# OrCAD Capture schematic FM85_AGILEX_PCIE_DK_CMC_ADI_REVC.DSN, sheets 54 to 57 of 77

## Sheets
54 PWR - VCC -1: size Custom
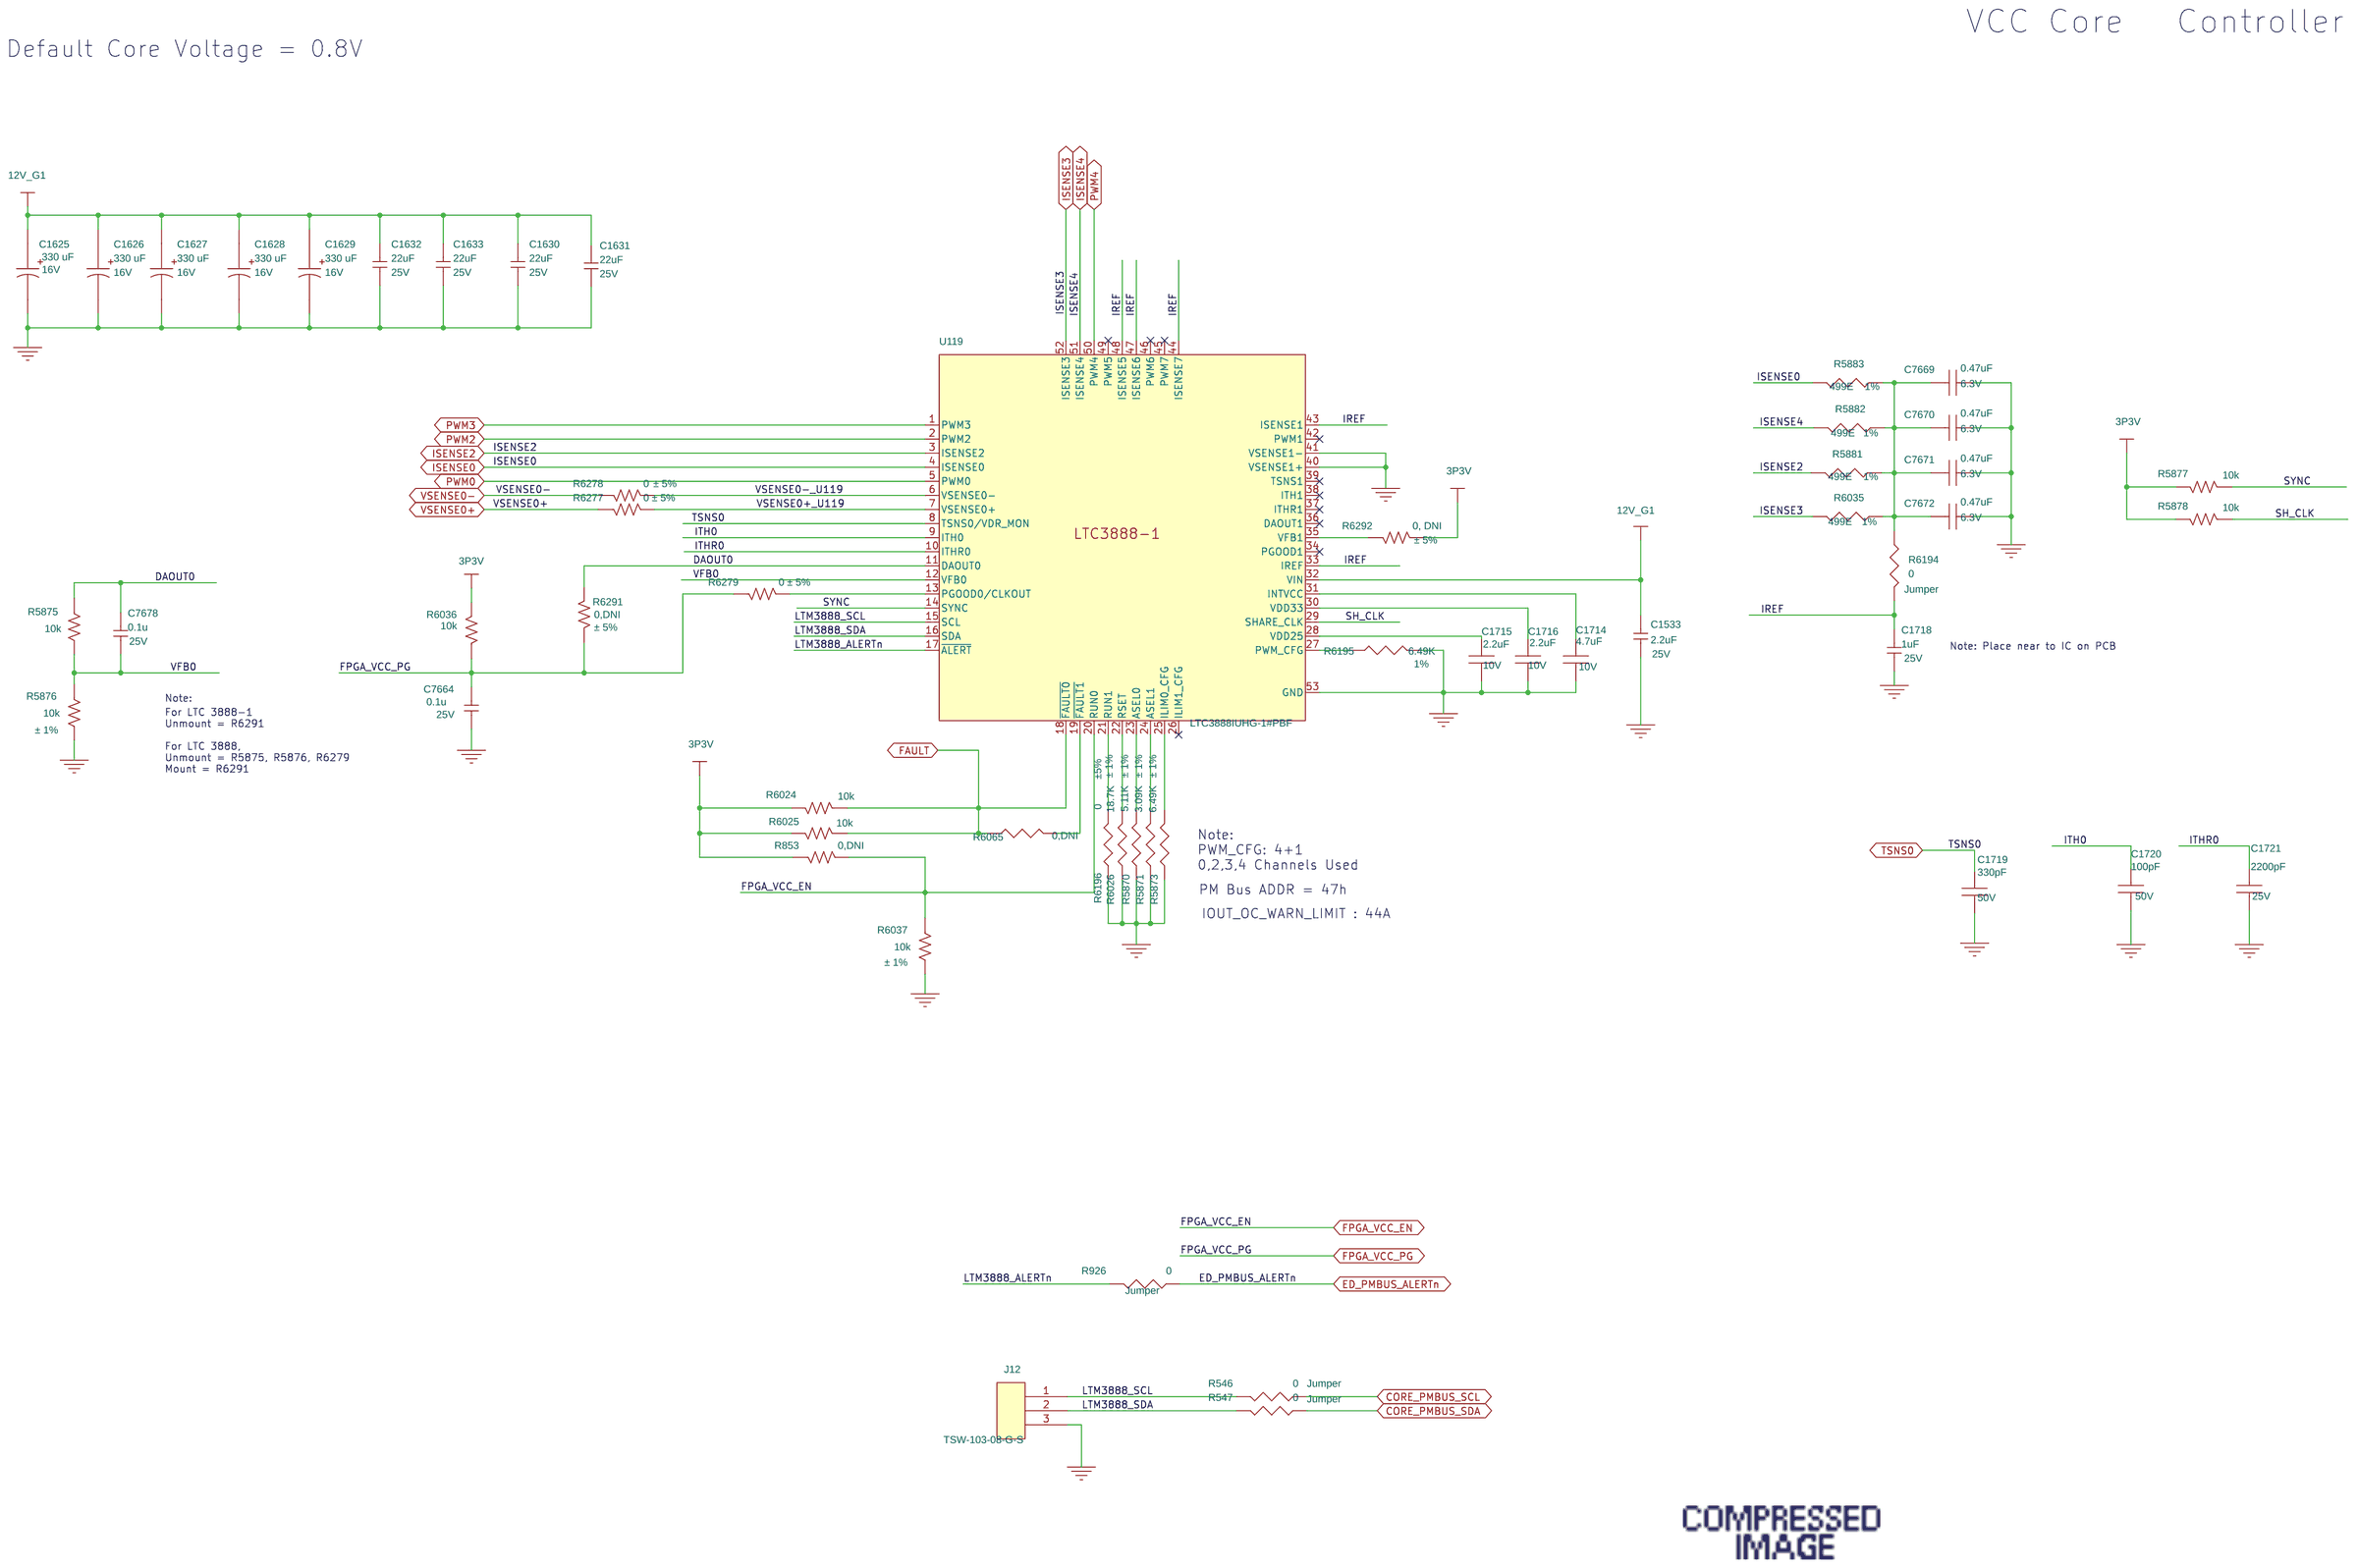
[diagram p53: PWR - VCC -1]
55 PWR - VCC -2: size Custom
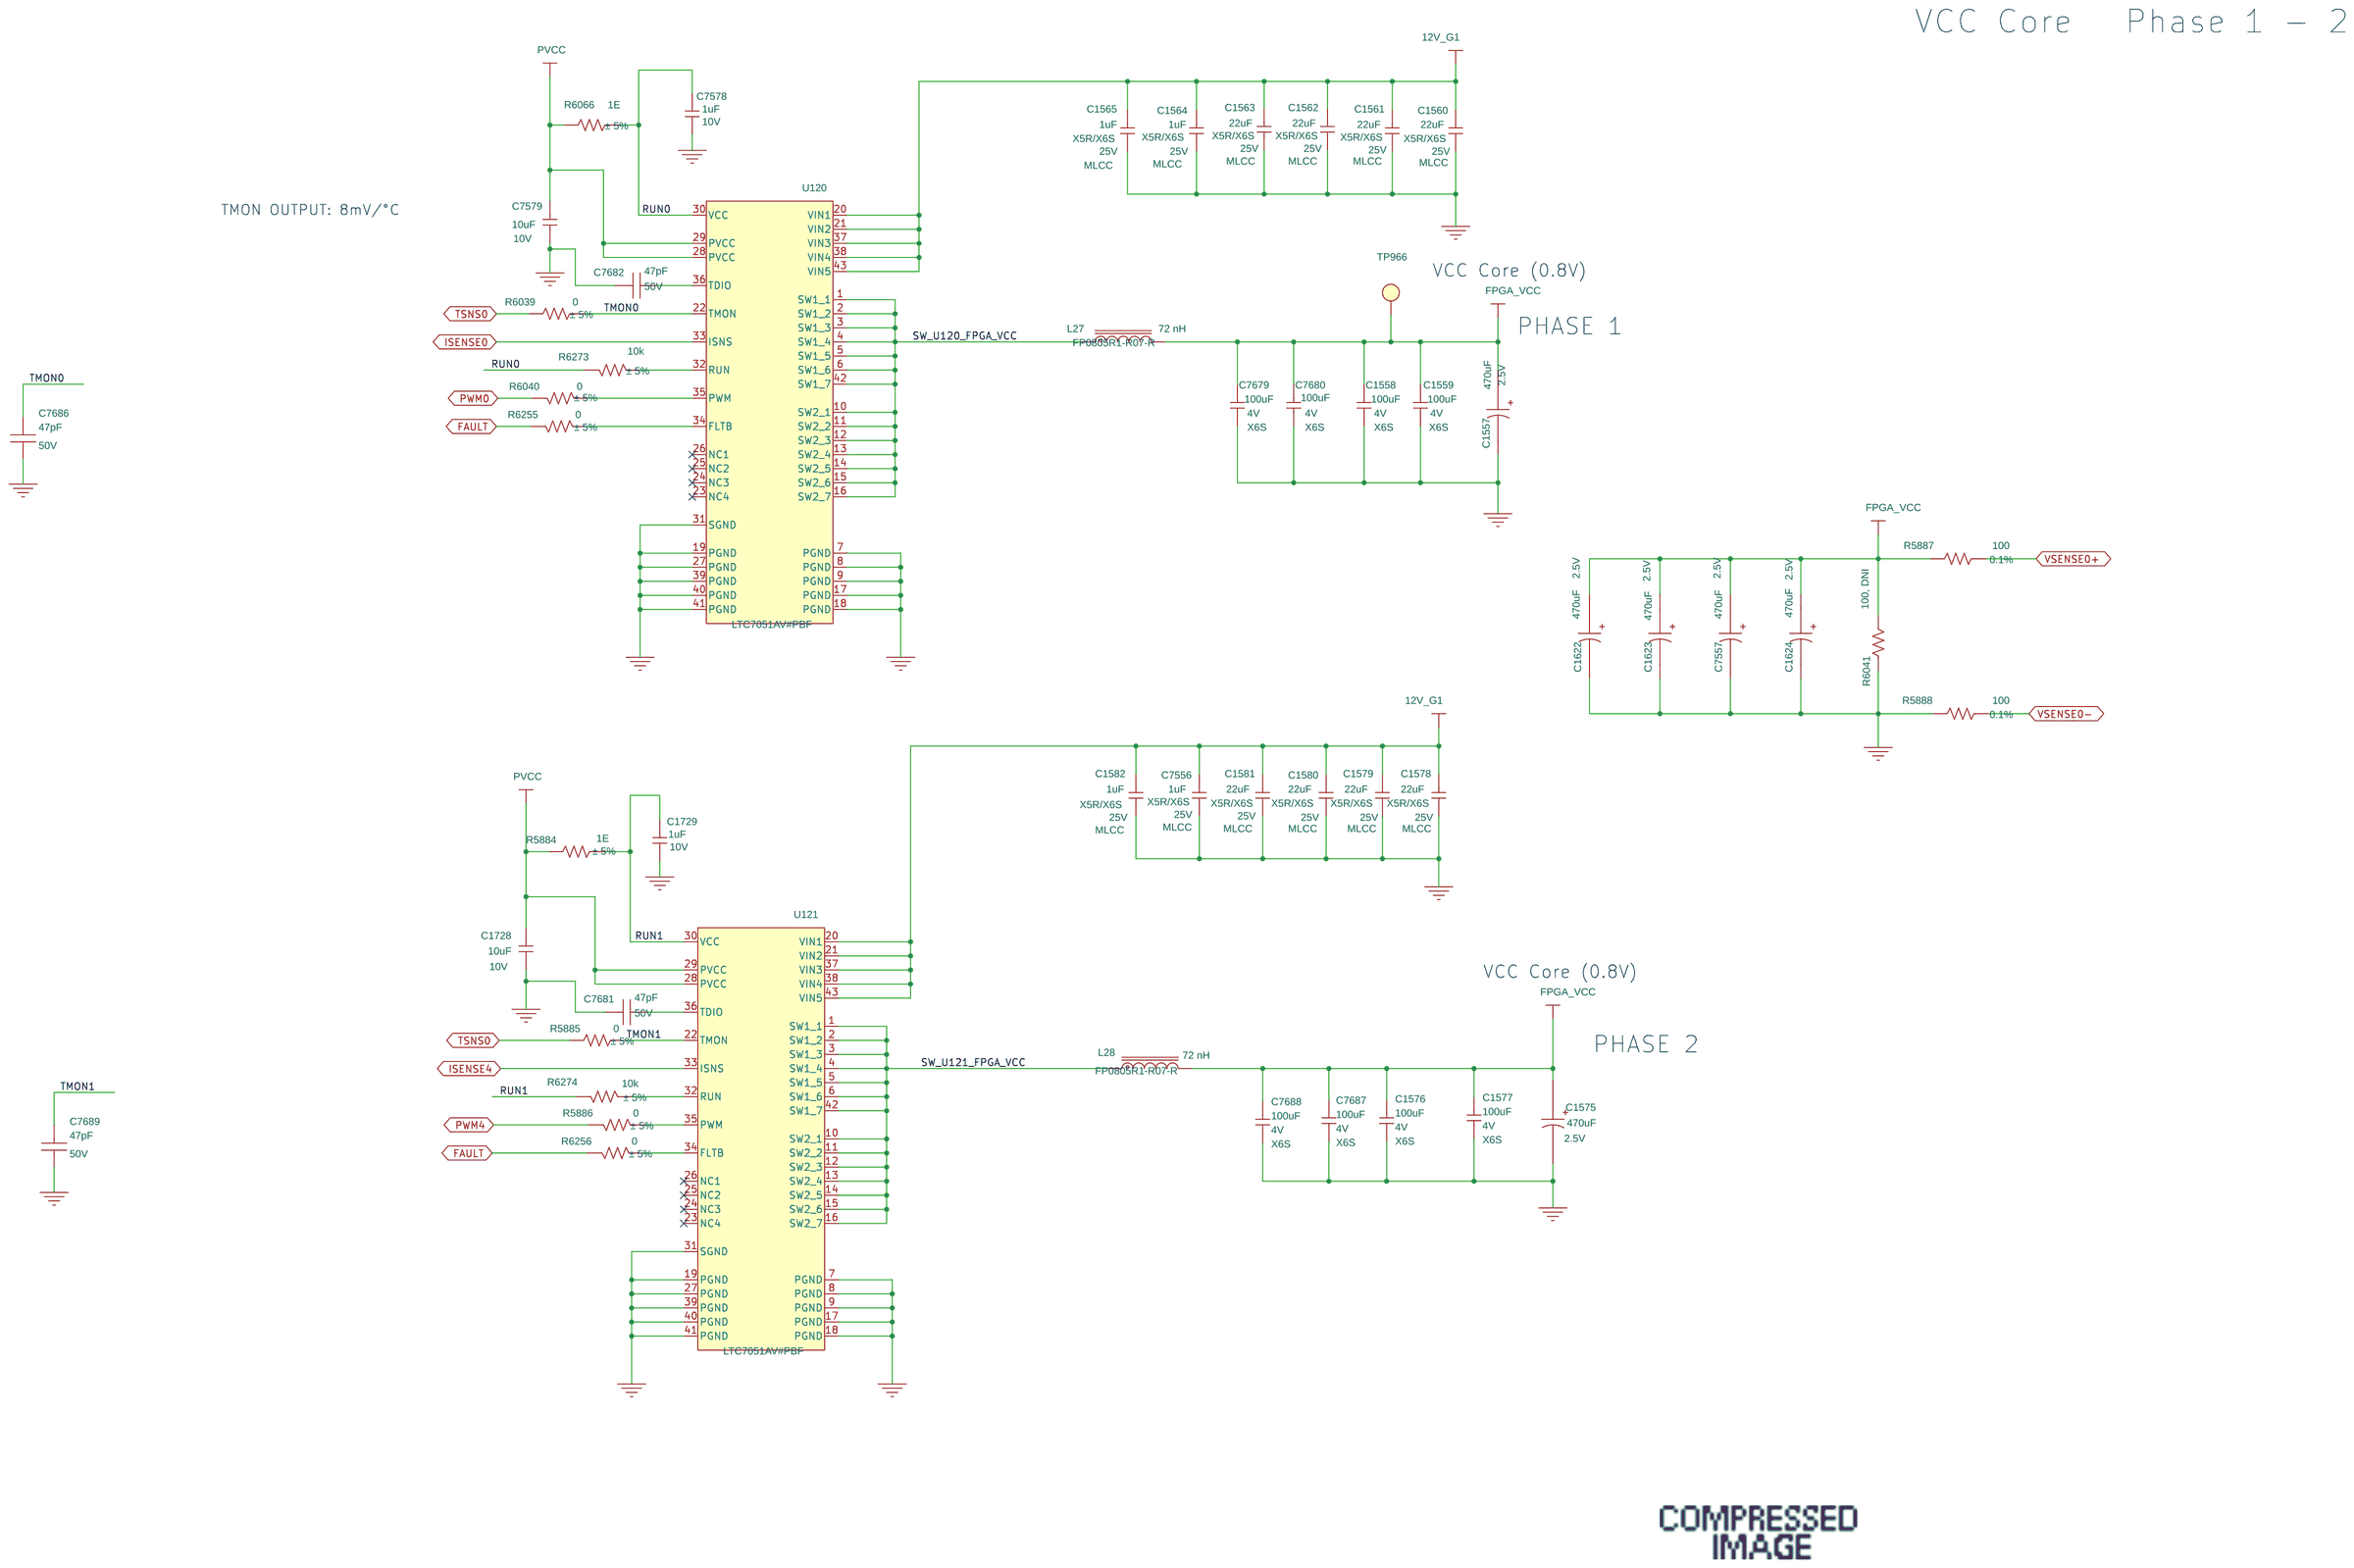
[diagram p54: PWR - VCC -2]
56 PWR - VCC - 3: size Custom
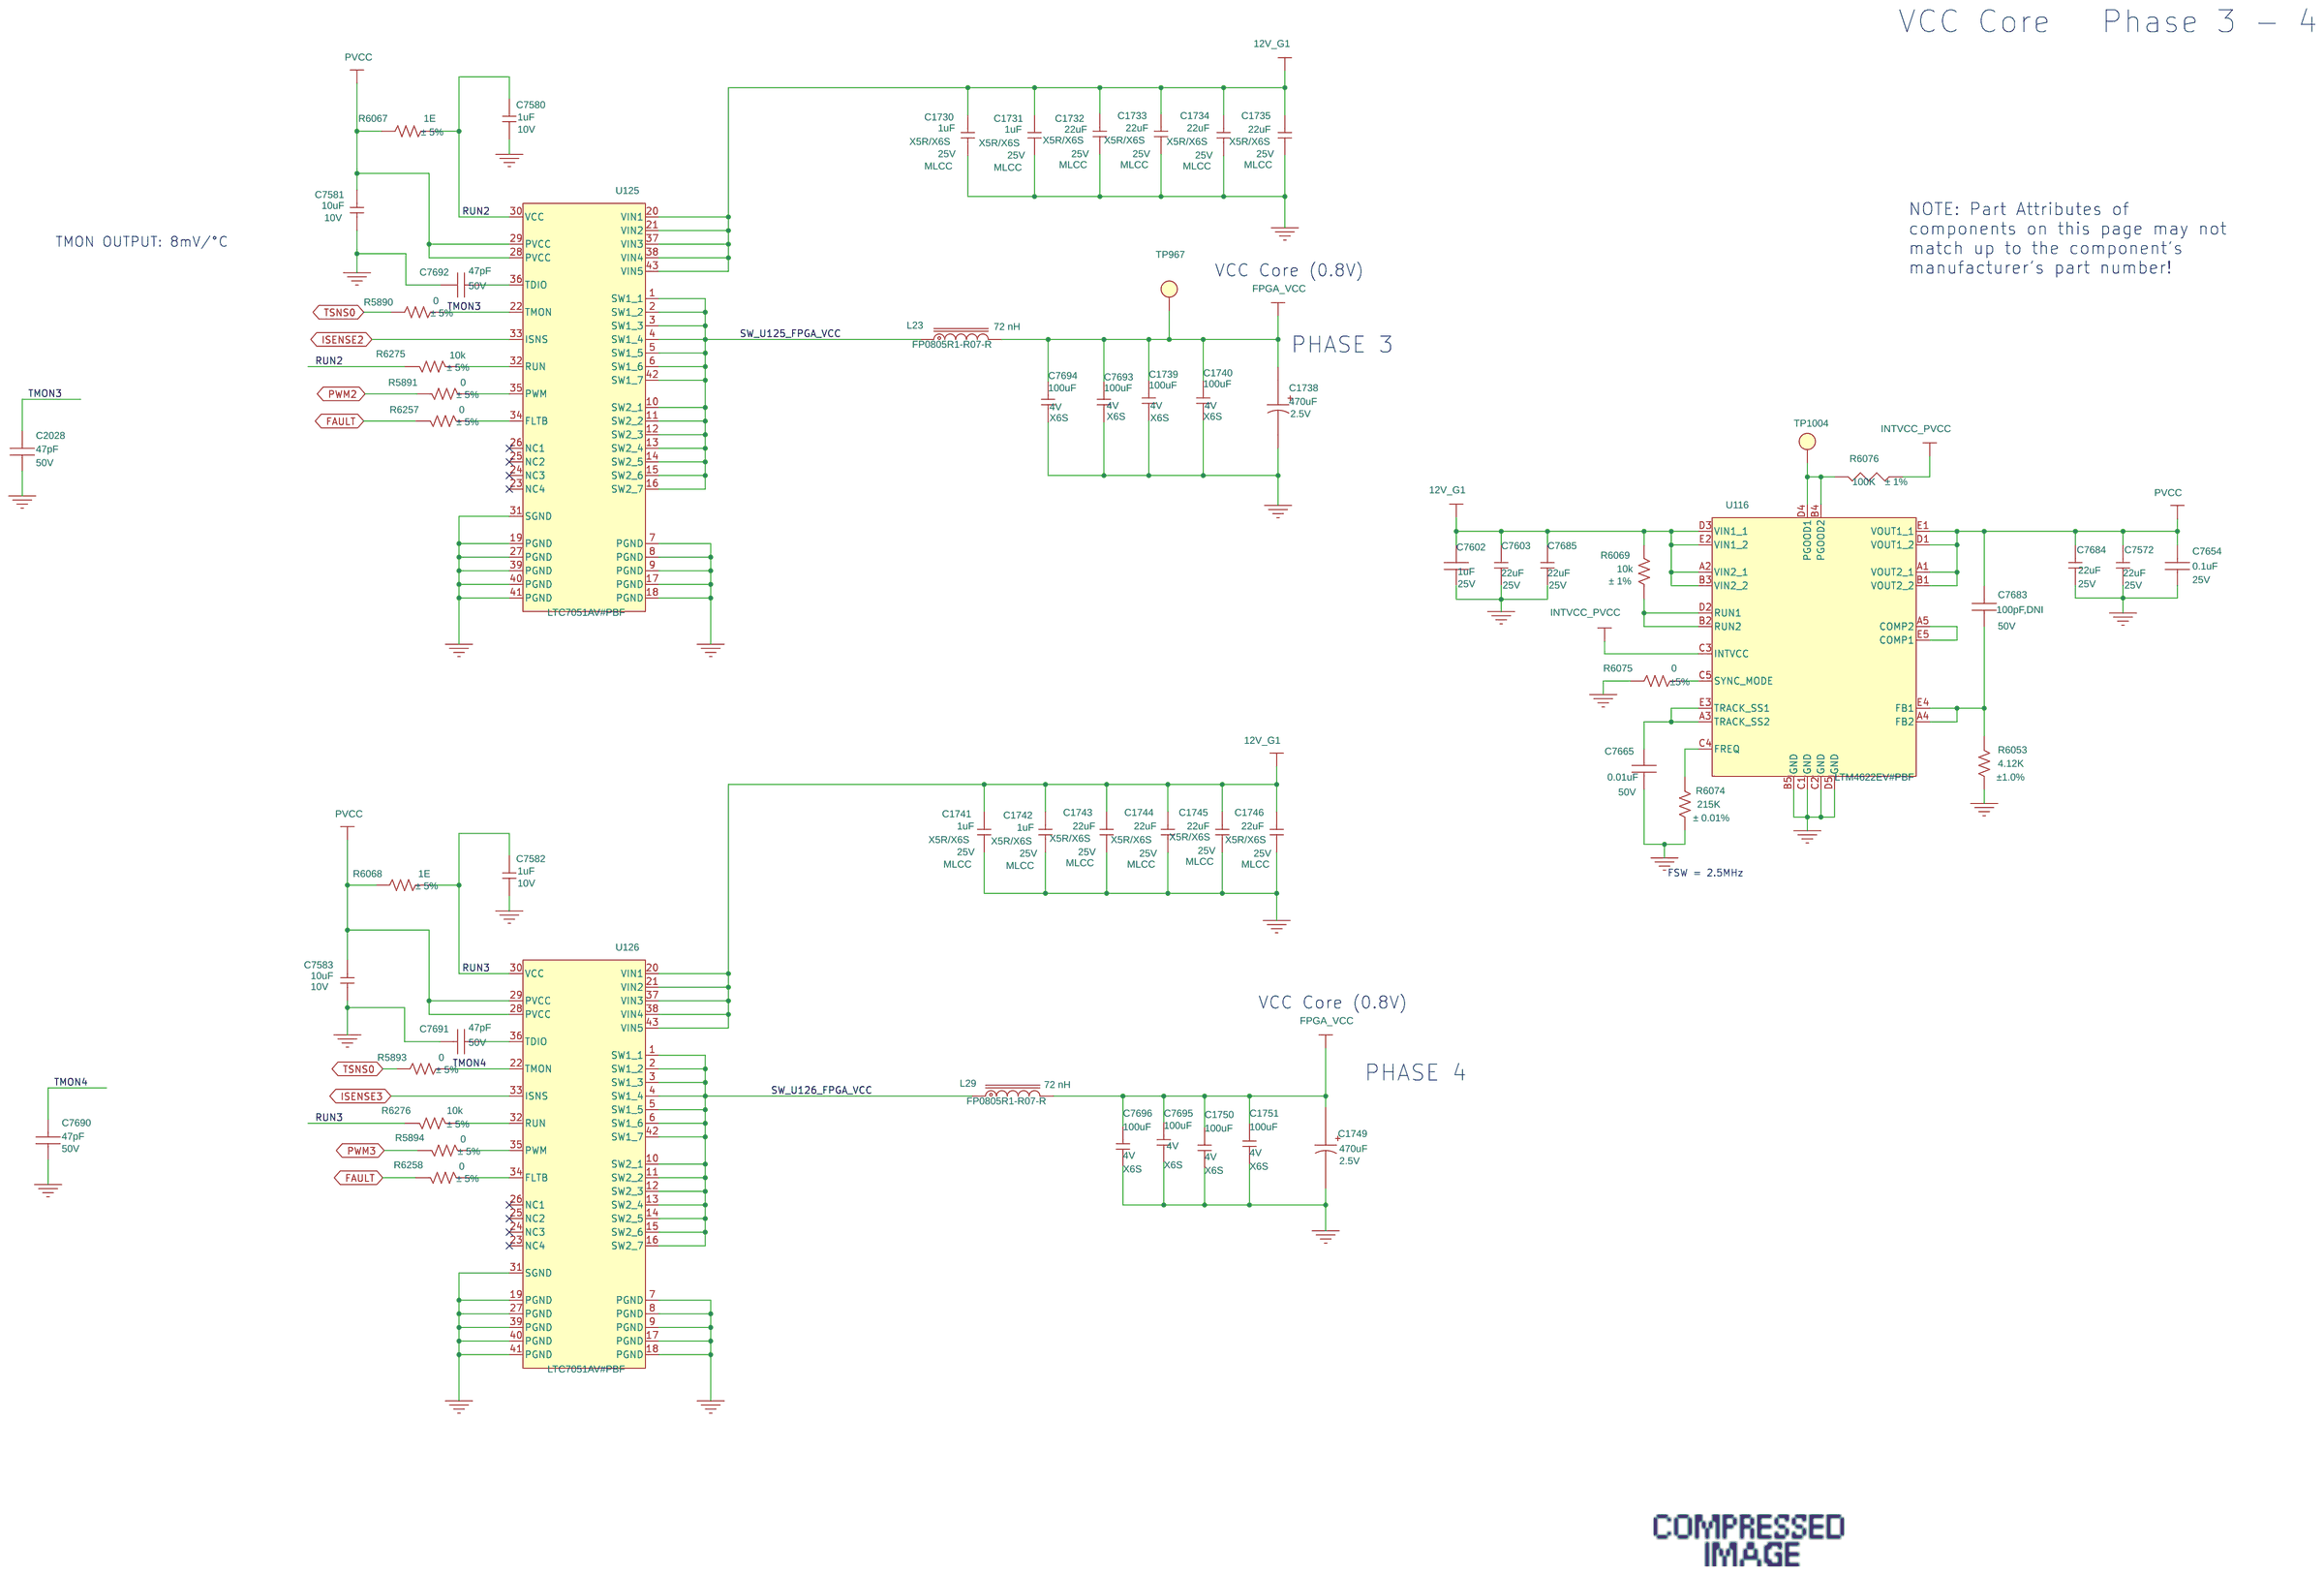
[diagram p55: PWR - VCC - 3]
57 PWR - 12V to 5V: size C
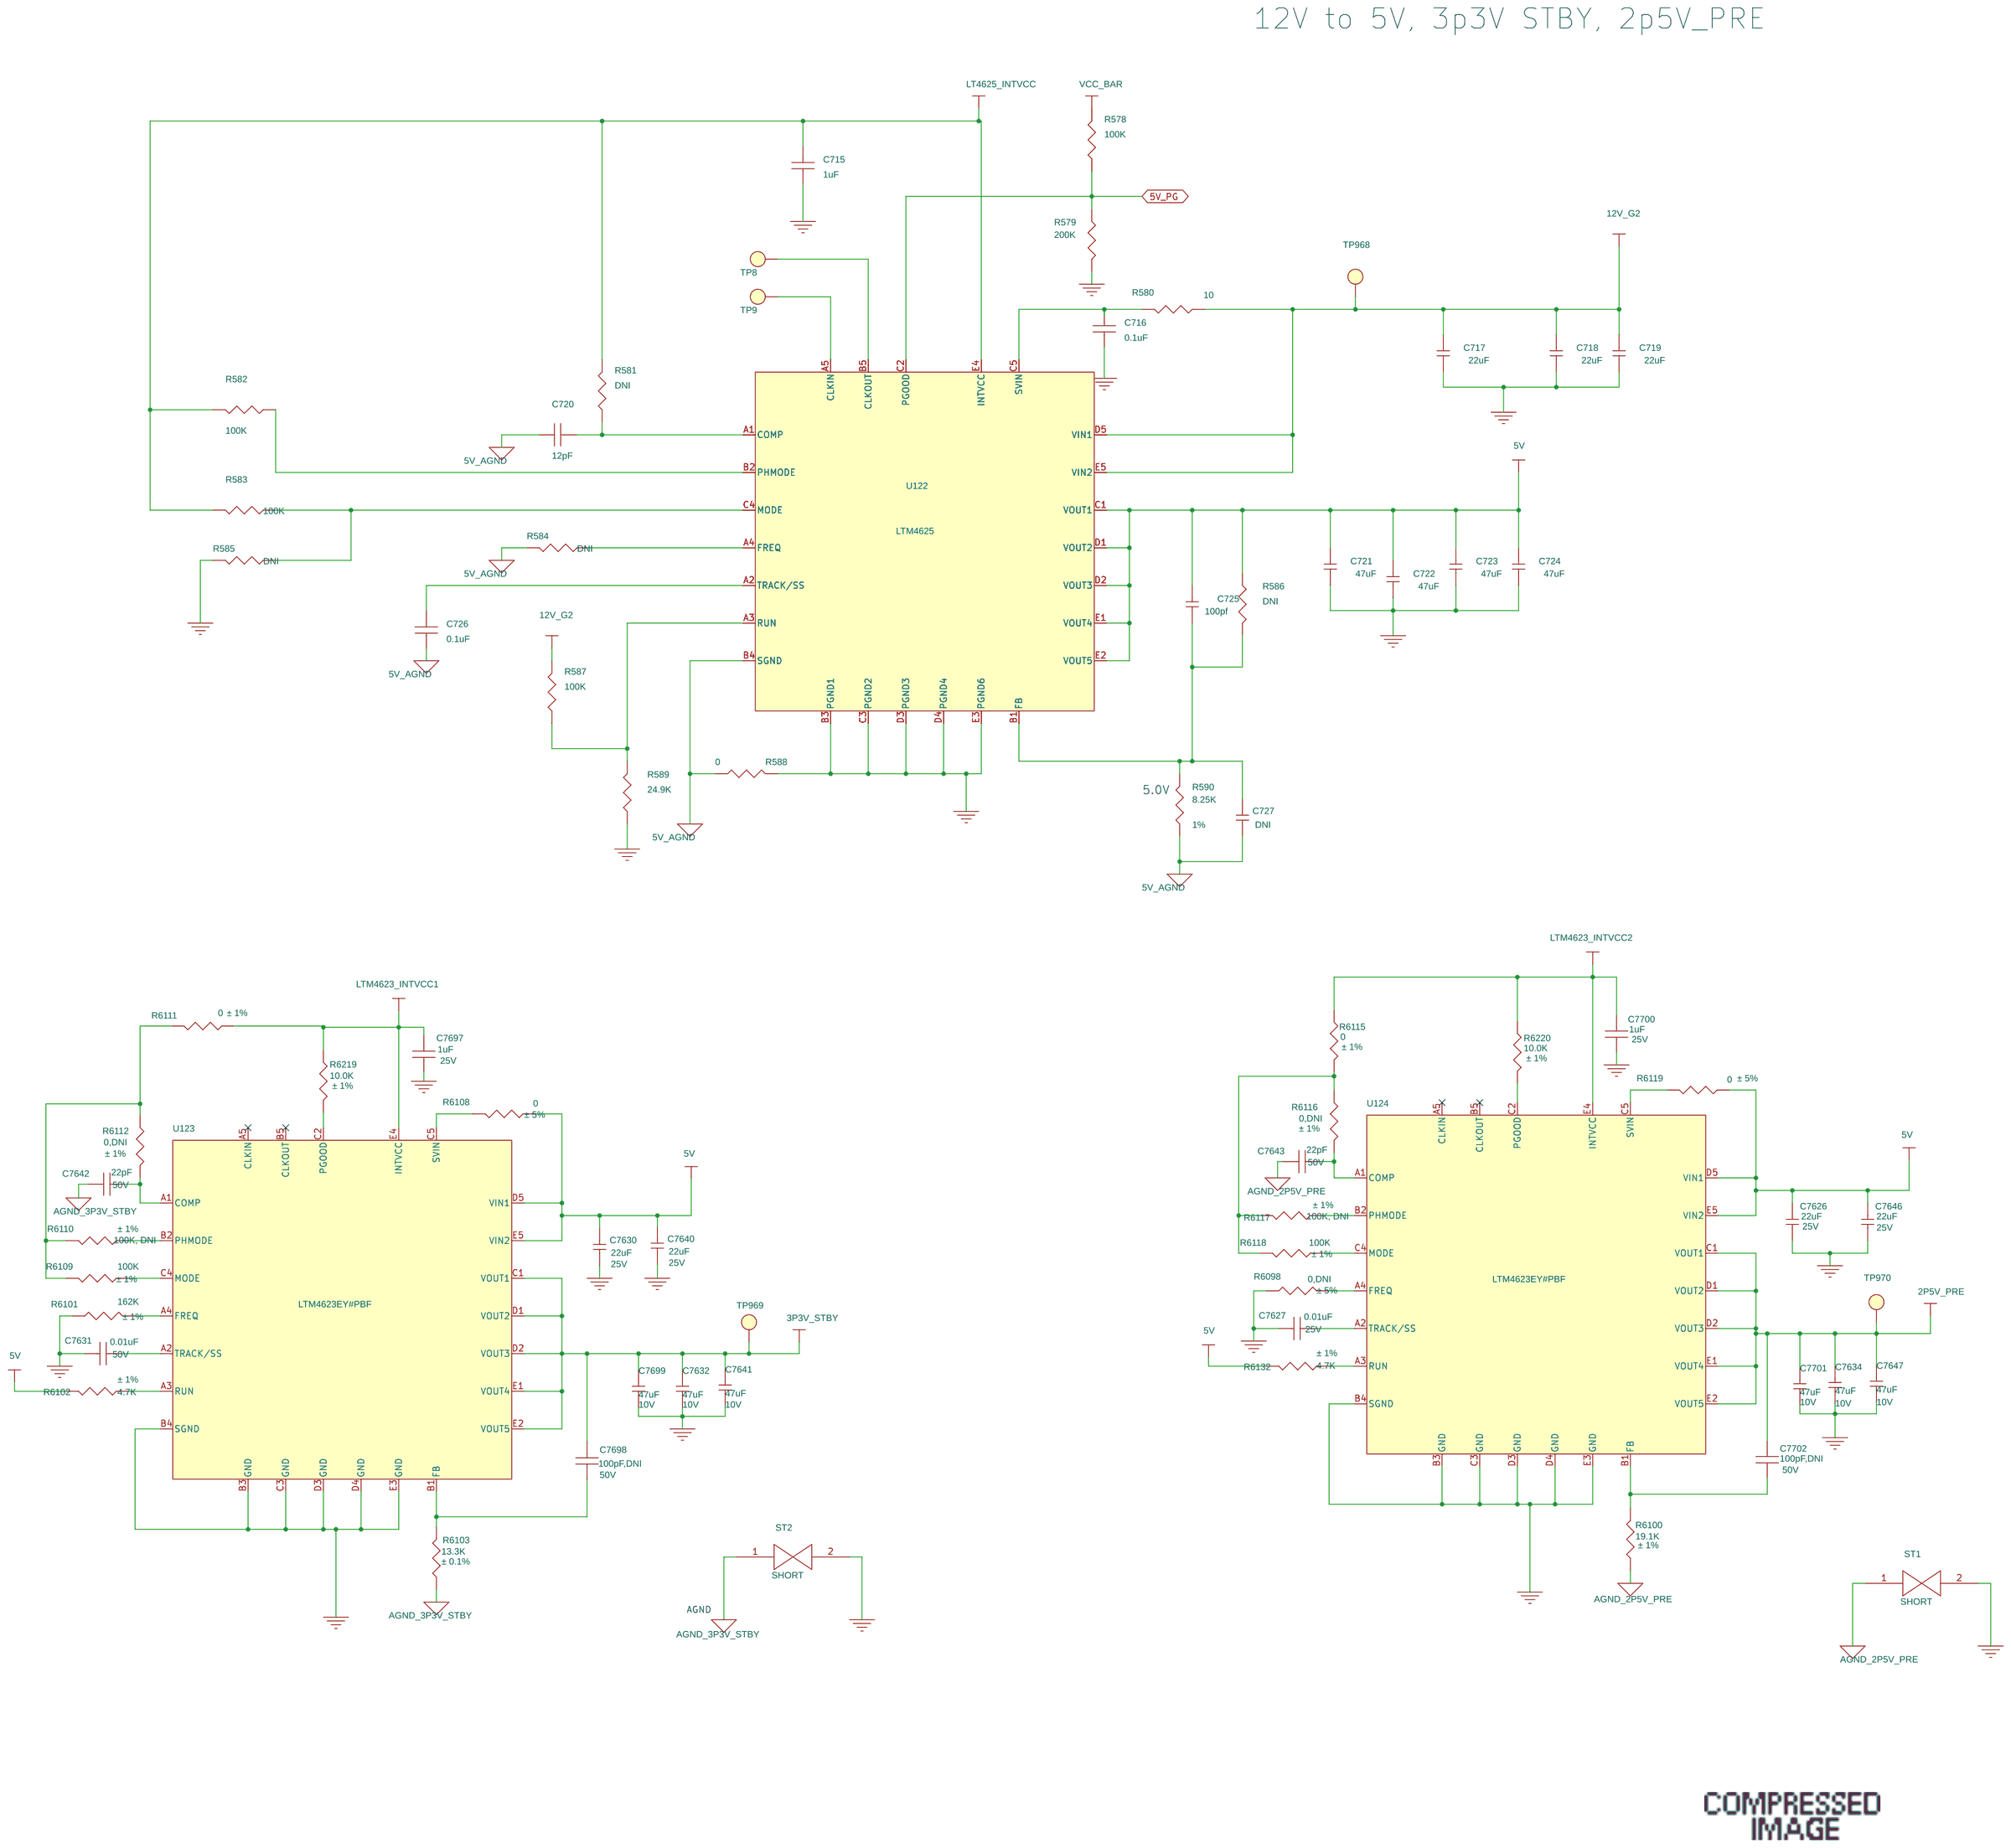
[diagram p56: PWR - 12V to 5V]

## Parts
sheet PWR - 12V to 5V
C715  1uF  [0402]
C716  0.1uF  [0402]
C717  22uF  [1206]
C718  22uF  [1206]
C719  22uF  [1206]
C720  12pF  [0402]
C721  47uF  [1206]
C722  47uF  [1206]
C723  47uF  [1206]
C724  47uF  [1206]
C725  100pf  [0402]
C726  0.1uF  [0402]
C727  DNI  [C0402]
C7626  22uF  [1206]
C7627  0.01uF  [0402]
C7630  22uF  [1206]
C7631  0.01uF  [0402]
C7632  47uF  [C1206]
C7634  47uF  [C1206]
C7640  22uF  [1206]
C7641  47uF  [C1206]
C7642  22pF  [0603]
C7643  22pF  [0603]
C7646  22uF  [1206]
C7647  47uF  [C1206]
C7697  1uF  [0402]
C7698  100pF,DNI  [0402]
C7699  47uF  [C1206]
C7700  1uF  [0402]
C7701  47uF  [C1206]
C7702  100pF,DNI  [0402]
R578  100K  [0402]
R579  200K  [0402]
R580  10  [0402]
R581  DNI  [0402]
R582  100K  [0402]
R583  100K  [0402]
R584  DNI  [0402]
R585  DNI  [0402]
R586  DNI  [0402]
R587  100K  [0402]
R588  0  [0402]
R589  24.9K  [0402]
R590  8.25K  [0402]
R6098  0,DNI  [0402]
R6100  19.1K  [0402]
R6101  162K  [RC0402]
R6102  4.7K  [0402]
R6103  13.3K  [0402]
R6108  0  [0402]
R6109  100K  [0402]
R6110  100K, DNI  [0402]
R6111  0  [0402]
R6112  0,DNI  [0402]
R6115  0  [0402]
R6116  0,DNI  [0402]
R6117  100K, DNI  [0402]
R6118  100K  [0402]
R6119  0  [0402]
R6132  4.7K  [0402]
R6219  10.0K  [0402]
R6220  10.0K  [0402]
ST1  SHORT  [SHORT]
ST2  SHORT  [SHORT]
TP8  TESTPOINT  [30MIL_TP]
TP9  TESTPOINT  [30MIL_TP]
TP968  TESTPOINT  [30MIL_TP]
TP969  TESTPOINT  [30MIL_TP]
TP970  TESTPOINT  [30MIL_TP]
U122  LTM4625  [BGA25]
U123  LTM4623EY#PBF  [BGA25C127P5X5_625X625X262]
U124  LTM4623EY#PBF  [BGA25C127P5X5_625X625X262]
sheet PWR - VCC -1
C1533  2.2uF  [0402]
C1625  330 uF  [CT7343-43]
C1626  330 uF  [CT7343-43]
C1627  330 uF  [CT7343-43]
C1628  330 uF  [CT7361-20]
C1629  330 uF  [CT7343-43]
C1630  22uF  [CAPC3216X135L50N]
C1631  22uF  [CAPC3216X135L50N]
C1632  22uF  [CAPC3216X135L50N]
C1633  22uF  [CAPC3216X135L50N]
C1714  4.7uF  [0402]
C1715  2.2uF  [0603]
C1716  2.2uF  [0603]
C1718  1uF  [0402]
C1719  330pF  [0603]
C1720  100pF  [0402]
C1721  2200pF  [0402]
C7664  0.1u  [CAPC1005X60L20L]
C7669  0.47uF  [0402]
C7670  0.47uF  [0402]
C7671  0.47uF  [0402]
C7672  0.47uF  [0402]
C7678  0.1u  [CAPC1005X60L20L]
J12  TSW-103-08-G-S  [1x3_HDR_TH]
R546  0  [0402]
R547  0  [0402]
R853  0,DNI  [RESC1005X40L20L]
R926  0  [0402]
R5870  5.11K  [0402]
R5871  3.09K  [0402]
R5873  6.49K  [0402]
R5875  10k  [0402]
R5876  10k  [0402]
R5877  10k  [0402]
R5878  10k  [0402]
R5881  499E  [0402]
R5882  499E  [0402]
R5883  499E  [0402]
R6024  10k  [0402]
R6025  10k  [0402]
R6026  18.7K  [0402]
R6035  499E  [0402]
R6036  10k  [0402]
R6037  10k  [0402]
R6065  0,DNI  [0402]
R6194  0  [0402]
R6195  6.49K  [0402]
R6196  0  [0402]
R6277  0  [RESC1005X40L20L]
R6278  0  [RESC1005X40L20L]
R6279  0  [RESC1005X40L20L]
R6291  0,DNI  [RESC1005X40L20L]
R6292  0, DNI  [RESC1005X40L20L]
U119  LTC3888IUHG-1#PBF  [QFN40P500X800X80-53N]
sheet PWR - VCC -2
C1557  470uF  [CAPMP7343X300L130X240N_p079in]
C1558  100uF  [CAPC2012X110L50L]
C1559  100uF  [CAPC2012X110L50L]
C1560  22uF  [CAPC3216X135L50N]
C1561  22uF  [CAPC3216X135L50N]
C1562  22uF  [CAPC3216X135L50N]
C1563  22uF  [CAPC3216X135L50N]
C1564  1uF  [capc1005x60l20l]
C1565  1uF  [capc1005x60l20l]
C1575  470uF  [CAPMP7343X300L130X240N_p079in]
C1576  100uF  [CAPC2012X110L50L]
C1577  100uF  [CAPC2012X110L50L]
C1578  22uF  [CAPC3216X135L50N]
C1579  22uF  [CAPC3216X135L50N]
C1580  22uF  [CAPC3216X135L50N]
C1581  22uF  [CAPC3216X135L50N]
C1582  1uF  [capc1005x60l20l]
C1622  470uF  [CAPMP7343X300L130X240N_p079in]
C1623  470uF  [CAPMP7343X300L130X240N_p079in]
C1624  470uF  [CAPMP7343X300L130X240N_p079in]
C1728  10uF  [0402]
C1729  1uF  [0402]
C7556  1uF  [capc1005x60l20l]
C7557  470uF  [CAPMP7343X300L130X240N_p079in]
C7578  1uF  [0402]
C7579  10uF  [0402]
C7679  100uF  [CAPC2012X110L50L]
C7680  100uF  [CAPC2012X110L50L]
C7681  47pF  [0402]
C7682  47pF  [0402]
C7686  47pF  [0402]
C7687  100uF  [CAPC2012X110L50L]
C7688  100uF  [CAPC2012X110L50L]
C7689  47pF  [0402]
L27  72 nH  [IND_FP0805-CUS]
L28  72 nH  [IND_FP0805-CUS]
R5884  1E  [RESC1005X40L20L]
R5885  0  [RESC1005X40L20L]
R5886  0  [RESC1005X40L20L]
R5887  100  [RESC1005X40L20L]
R5888  100  [RESC1005X40L20L]
R6039  0  [RESC1005X40L20L]
R6040  0  [RESC1005X40L20L]
R6041  100, DNI  [RESC1608X60L27N]
R6066  1E  [RESC1005X40L20L]
R6255  0  [RESC1005X40L20L]
R6256  0  [RESC1005X40L20L]
R6273  10k  [0402]
R6274  10k  [0402]
TP966  TESTPOINT  [30MIL_TP]
U120  LTC7051AV#PBF  [ANALOG_LQFN-42P]
U121  LTC7051AV#PBF  [ANALOG_LQFN-42P]
sheet PWR - VCC - 3
C1730  1uF  [0402]
C1731  1uF  [0402]
C1732  22uF  [CAPC3216X135L50N]
C1733  22uF  [CAPC3216X135L50N]
C1734  22uF  [CAPC3216X135L50N]
C1735  22uF  [CAPC3216X135L50N]
C1738  470uF  [CAPMP7343X300L130X240N_p079in]
C1739  100uF  [CAPC2012X110L50L]
C1740  100uF  [CAPC2012X110L50L]
C1741  1uF  [0402]
C1742  1uF  [0402]
C1743  22uF  [CAPC3216X135L50N]
C1744  22uF  [CAPC3216X135L50N]
C1745  22uF  [CAPC3216X135L50N]
C1746  22uF  [CAPC3216X135L50N]
C1749  470uF  [CAPMP7343X300L130X240N_p079in]
C1750  100uF  [CAPC2012X110L50L]
C1751  100uF  [CAPC2012X110L50L]
C2028  47pF  [0402]
C7572  22uF  [CAPC3216X135L50N]
C7580  1uF  [0402]
C7581  10uF  [0402]
C7582  1uF  [0402]
C7583  10uF  [0402]
C7602  1uF  [0402]
C7603  22uF  [CAPC3216X135L50N]
C7654  0.1uF  [0402]
C7665  0.01uF  [0402]
C7683  100pF,DNI  [0402]
C7684  22uF  [CAPC3216X135L50N]
C7685  22uF  [CAPC3216X135L50N]
C7690  47pF  [0402]
C7691  47pF  [0402]
C7692  47pF  [0402]
C7693  100uF  [CAPC2012X110L50L]
C7694  100uF  [CAPC2012X110L50L]
C7695  100uF  [CAPC2012X110L50L]
C7696  100uF  [CAPC2012X110L50L]
L23  72 nH  [IND_FP0805-CUS]
L29  72 nH  [IND_FP0805-CUS]
R5890  0  [RESC1005X40L20L]
R5891  0  [RESC1005X40L20L]
R5893  0  [RESC1005X40L20L]
R5894  0  [RESC1005X40L20L]
R6053  4.12K  [0402]
R6067  1E  [RESC1005X40L20L]
R6068  1E  [RESC1005X40L20L]
R6069  10k  [0402]
R6074  215K  [0402]
R6075  0  [RESC1005X40L20L]
R6076  100K  [0402]
R6257  0  [RESC1005X40L20L]
R6258  0  [RESC1005X40L20L]
R6275  10k  [0402]
R6276  10k  [0402]
TP967  TESTPOINT  [30MIL_TP]
TP1004  TESTPOINT  [30MIL_TP]
U116  LTM4622EV#PBF  [LGA25C127P5X5_625X625X192N]
U125  LTC7051AV#PBF  [ANALOG_LQFN-42P]
U126  LTC7051AV#PBF  [ANALOG_LQFN-42P]

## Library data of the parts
C715 = CAP: CAP - CER, 1UF, 25V, 10%, X5R, 0402; Item Num: H29050-001; Lead Free Status: Yes; Manufacturer: TDK Electronics; Manufacturer Part Num: CGB2A1X5R1E105K033BC; Num Pins: 2; Part Class: CAPACITORS; RoHS Compliant: Yes
C716 C726 = CAP: CAPC,  X7R, 0402, 0.1uF, 25V, ±20%; AGILE_LINK: http://sj-agile9app/Agile/PLMServlet?action=OpenEmailObject&classid=10000&objid=213459527; Item Num: K13660-001; LIFECYCLE_PHASE: Active; Lead Free Status: Lead Free; MFR_LIFECYCLE: Active; Manufacturer: Murata; Manufacturer Part Num: GRM155R71E104KE14D; Num Pins: 2; PART_SUBCLASS: CAPACITORS; Part Class: CAPACITORS; RATED_VOLTAGE: 25V; RoHS Compliant: RoHS Compliant; TOLERANCE: +80%/-20%
C717-C719 = Cap,_NP,_1206: CAP - CER, 22UF, 25V, 10%, X5R, 1206; Item Num: K28232-001; Manufacturer: Murata; Manufacturer Part Num: GRM31CR61E226KE15L
C720 = CAP: CAP - 12PF, 50V, +/-5%, CERAMIC, 0402 SMD; AGILE_LINK: http://sj-agile9app/Agile/PLMServlet?action=OpenEmailObject&classid=10000&objid=257385742; Item Num: A36095-043; LIFECYCLE_PHASE: Active; Lead Free Status: Lead Free; MFR_LIFECYCLE: Active; Manufacturer: Murata; Manufacturer Part Num: GRM1555C1H120JA01D; Num Pins: 2; PART_SUBCLASS: CAPACITORS; RATED_VOLTAGE: 50V; RoHS Compliant: RoHS Compliant; TOLERANCE: +/-5%
C721-C724 = Cap,_NP,_1206: CAP - CER 47UF 10V 20% X5R 1206; Item Num: K13655-001; Manufacturer: TDK Electronics; Manufacturer Part Num: C3216X5R1A476M160AB
C725 = Cap,_NP,_0402: CAP, CERAMIC, 100pF, 0402, 5%, 50VDC, NPO; Item Num: K13768-001; Manufacturer: Murata; Manufacturer Part Num: GRM1555C1H101JA01D
C727 = Cap,_NP,_0402: CAP - CER, 15PF, 50V, +/-5%, C0G, 0402 SMD; Item Num: A36095-047; Manufacturer: Murata; Manufacturer Part Num: GRM1555C1H150JA01D
C7626 C7630 C7640 C7646 = Cap,_NP,_1206: CAP - CER, 22UF, 25V, 10%, X5R, 1206; Item Num: K28232-001; Manufacturer: Murata; Manufacturer Part Num: GRM31CR61E226KE15L; RATED_VOLTAGE: 25V
C7627 = CAP: CAP - CER, 10NF, 50V, +/-10%, X7R, 0402 SMD; CAPACITANCE: 0.1uF; Item Num: A36096-100; LIFECYCLE_PHASE: Active; Lead Free Status: Lead Free; MFR_LIFECYCLE: Active; Manufacturer: Murata; Manufacturer Part Num: GRM155R71H103KA88D; Num Pins: 2; PART_SUBCLASS: CAPACITORS; Part Class: CAPACITORS; RATED_VOLTAGE: 25V; RoHS Compliant: RoHS Compliant
C7631 = CAP: CAP - CER, 10NF, 50V, +/-10%, X7R, 0402 SMD; CAPACITANCE: 0.1uF; Item Num: A36096-100; LIFECYCLE_PHASE: Active; Lead Free Status: Lead Free; MFR_LIFECYCLE: Active; Manufacturer: Murata; Manufacturer Part Num: GRM155R71H103KA88D; Num Pins: 2; PART_SUBCLASS: CAPACITORS; Part Class: CAPACITORS; RATED_VOLTAGE: 50V; RoHS Compliant: RoHS Compliant
C7632 C7634 C7641 C7647 C7699 C7701 = Cap,_NP,_1206: CAP - CER 47UF 10V 20% X5R 1206; Item Num: K13655-001; Manufacturer: TDK Electronics; Manufacturer Part Num: C3216X5R1A476M160AB; RATED_VOLTAGE: 10V
C7642 C7643 = CAP_NP: CAPC,C0G,0603,22.000PF,50.000V,+/- 5%,; Item Num: M23241-001; Manufacturer: Murata; Manufacturer Part Num: GRM1885C1H220JA01J; RATED_VOLTAGE: 50V
C7697 C7700 = CAP: CAP - CER, 1UF, 25V, 10%, X5R, 0402; Item Num: H29050-001; Lead Free Status: Yes; Manufacturer: TDK Electronics; Manufacturer Part Num: CGB2A1X5R1E105K033BC; Num Pins: 2; Part Class: CAPACITORS; RATED_VOLTAGE: 25V; RoHS Compliant: Yes
C7698 = CAP: CAP CER 100PF 50V X7R 0402; CAPACITANCE: 1000pF; Dielectric: X7R; IPN No: A36095-026; Item Num: A36095-026; LIFECYCLE_PHASE: Active; Lead Free Status: Lead Free; Manufacturer: AVX; Manufacturer Part Num: 04025C101KAT2A; Num Pins: 2; Part Class: CAPACITORS; RATED_VOLTAGE: 50V; RoHS Compliant: RoHS Compliant; Tolerance: 10%
C7702 = CAP: CAP, CERAMIC, 100pF, 0402, 5%, 50VDC, NPO; CAPACITANCE: 1000pF; Dielectric: X7R; IPN No: A36095-026; Item Num: A36095-026; LIFECYCLE_PHASE: Active; Lead Free Status: Lead Free; Manufacturer: Murata; Manufacturer Part Num: 04025C101KAT2A; Num Pins: 2; Part Class: CAPACITORS; RATED_VOLTAGE: 50V; RoHS Compliant: RoHS Compliant; Tolerance: 10%
R578 R582 R583 R587 = RESISTOR: RES, 100K OHMS, 1.0%, 1/16W, 0402; AGILE_LINK: http://sj-agile9app/Agile/PLMServlet?action=OpenEmailObject&classid=10000&objid=146932246; Item Num: E86804-001; LIFECYCLE_PHASE: Active; MFR_LIFECYCLE: Active; Manufacturer: Panasonic; Manufacturer Part Num: ERJ-2RKF1003X; Num Pins: 2; PART_SUBCLASS: RESISTORS; POWER: 1/10W; RoHS Compliant: RoHS Compliant; TOLERANCE: +/-1%
R579 = RES: RES - 200K OHM, 1/16W, 1%, 0402 SMD; Item Num: A93548-186; Manufacturer: Panasonic; Manufacturer Part Num: ERJ-2RKF2003X; Package: SMD; Part Class: RESISTORS; Type: Resistor
R580 = RESISTOR: RES, 10 OHM, 1%, 1/16W, 0402; AGILE_LINK: http://sj-agile9app/Agile/PLMServlet?action=OpenEmailObject&classid=10000&objid=146932246; Item Num: A80345-001; LIFECYCLE_PHASE: Active; MFR_LIFECYCLE: Active; Manufacturer: Panasonic; Manufacturer Part Num: ERJ-2RKF10R0X; Num Pins: 2; PART_SUBCLASS: RESISTORS; POWER: 1/16W; RoHS Compliant: RoHS Compliant; TOLERANCE: +/-1%
R581 R584-R586 = RESISTOR: RES, 100K OHMS, 1.0%, 1/16W, 0402; AGILE_LINK: http://sj-agile9app/Agile/PLMServlet?action=OpenEmailObject&classid=10000&objid=146932246; Item Num: E86804-001; LIFECYCLE_PHASE: Active; MFR_LIFECYCLE: Active; Manufacturer: Panasonic; Manufacturer Part Num: ERJ-2RKF1003X; Num Pins: 2; PART_SUBCLASS: RESISTORS; POWER: 1/10W; RESISTANCE: 100K; RoHS Compliant: RoHS Compliant; TOLERANCE: +/-1%
R588 = RESISTOR: RES ZERO OHM 1/16W 5% 0402 SMD; Altera Part No.: P02-14020R; Item Num: H30887-001; LIFECYCLE_PHASE: Active; Lead Free Status: No; MFR_LIFECYCLE: Active; Manufacturer: Panasonic; Manufacturer Part Num: ERJ-2GE0R00X; Num Pins: 2; PART_SUBCLASS: RESISTORS; POWER: 1/16W; Part Class: RESISTORS; RoHS Compliant: RoHS Compliant; Tolerance: +/-5%
R589 = RESISTOR: RES - 24.9K OHM, 1/16W, 1%, 0402 SMD; Altera Part No.: P02-14020R; Item Num: A93548-187; Lead Free Status: No; Manufacturer: Vishay; Manufacturer Part Num: CRCW040224K9FKED; Num Pins: 2; Part Class: RESISTORS; Price: 0; RoHS Compliant: Yes; Tolerance: 1%
R590 = RESISTOR: RES,8.25K OHMS,1.0%,1/16W,0402; Item Num: A93548-195; Lead Free Status: No; Manufacturer: Panasonic; Manufacturer Part Num: ERJ-2RKF8251X; Mfr Prt #: ERJ-2RKF8251X; Num Pins: 2; Part Class: Resistors; Price: 0; RoHS Compliant: Yes; Tolerance: 1%
R6098 = RESISTOR: RES D,0402,0.00 OHM,5.00%,1/16W; Altera Part No.: P02-14020R; Item Num: A93549-001; LIFECYCLE_PHASE: Active; Lead Free Status: No; MFR_LIFECYCLE: Active; Manufacturer: YAGEO CORP.; Manufacturer Part Num: RC0402JR-070RL; Num Pins: 2; PART_SUBCLASS: RESISTORS; POWER: 1/16W; Part Class: RESISTORS; Price: 0; RESISTANCE: 0; RoHS Compliant: RoHS Compliant; Tolerance: ± 5%
R6100 = RESISTOR: RES 19.1K 1% 1/16W 0402; Item Num: L14017-001; Lead Free Status: No; Manufacturer: Panasonic; Manufacturer Part Num: ERJ-2RKF1912X; Manufacturer's Part No.: ERJ-2GEJ472X; Num Pins: 2; Part Class: RESISTORS; Price: 0; RoHS Compliant: Yes; Tolerance (%): ± 1%
R6101 = RESISTOR: RES, THICK FILM, 162K OHM, 1%, 0.063W, +/-100PPM/C, 0402, SMD; Altera Part No.: P02-14020R; Item Num: M85603-001; LIFECYCLE_PHASE: Active; Lead Free Status: No; MFR_LIFECYCLE: Active; Manufacturer: STACKPOLE ELECTRONICS; Manufacturer Part Num: RMCF0402FT162K; Num Pins: 2; PACK_TYPE: 0402; PART_NUMBER: RMCF0402FT162K; PART_SUBCLASS: RESISTORS; POWER: 1/16W; Part Class: RESISTORS; Price: 0; RoHS Compliant: RoHS Compliant; Tolerance: 1%; Tolerance (%): ± 1%; VOLTAGE: NA; WATTAGE: 0.063W
R6102 R6132 = RESISTOR: RES,4.70K OHMS,1.0%,1/16W,0402; Item Num: A93548-517; Lead Free Status: No; Manufacturer: Vishay; Manufacturer Part Num: CRCW04024K70FKED; Manufacturer's Part No.: ERJ-2GEJ472X; Num Pins: 2; Part Class: RESISTORS; Price: 0; RoHS Compliant: Yes; Tolerance (%): ± 1%
R6103 = RESISTOR: RES_D,0402,13.3kOHM,0.1%,1/16W,; Item Num: G85996-069; Lead Free Status: No; Manufacturer: WALSIN TECHNOLOGY CORP; Manufacturer Part Num: WF04T1332BTL; Manufacturer's Part No.: WF04T1332BTL; Num Pins: 2; Part Class: RESISTORS; Price: 0; RoHS Compliant: Yes; Tolerance (%): ± 0.1%
R6108 = RES_0_OHM_5%_1_16W_0402_SMD: RES D,0402,0.00 OHM,5.00%,1/16W; Item Num: A93549-001; Manufacturer: YAGEO CORP.; Manufacturer Part Num: RC0402JR-070RL; Tolerance: +/-5%; Tolerance (%): ± 5%
R6109 R6110 R6117 R6118 = RESISTOR: RES,100K OHMS,1.0%,1/16W,0402; Item Num: A78422-001; Lead Free Status: No; Manufacturer: Panasonic; Manufacturer Part Num: ERJ-2RKF1003X; Num Pins: 2; Part Class: Resistors; Price: 0; RoHS Compliant: Yes; Tolerance (%): ± 1%
R6111 R6115 = RESISTOR: RES D,0402,0.00 OHM,5.00%,1/16W; Item Num: A93549-001; Lead Free Status: No; Manufacturer: Panasonic; Manufacturer Part Num: ERJ-2RKF1003X; Num Pins: 2; Part Class: Resistors; RoHS Compliant: Yes; Tolerance (%): ± 1%
R6112 R6116 = RESISTOR: RES D,0402,0.00 OHM,5.00%,1/16W; Item Num: A93549-001; Lead Free Status: No; Manufacturer: Panasonic; Manufacturer Part Num: ERJ-2RKF1003X; Num Pins: 2; Part Class: Resistors; Price: 0; RoHS Compliant: Yes; Tolerance (%): ± 1%
R6119 = RES_0_OHM_5%_1_16W_0402_SMD: RES D,0402,0.00 OHM,5.00%,1/16W; Item Num: A93549-001; Manufacturer: YAGEO CORP.; Manufacturer Part Num: RC0402JR-070RL; Tolerance (%): ± 5%
R6219 R6220 = RESISTOR: RES,10.0K OHMS,1.0%,1/16W, 0402; AGILE_LINK: http://sj-agile9app/Agile/PLMServlet?action=OpenEmailObject&classid=10000&objid=146548997; Item Num: K28115-001; LIFECYCLE_PHASE: Active; Lead Free Status: No; MFR_LIFECYCLE: Active; Manufacturer: Panasonic; Manufacturer Part Num: ERJ-2RKF1002X; Num Pins: 2; PART_SUBCLASS: RESISTORS; POWER: 1/16W; RESISTANCE: 10K; RoHS Compliant: Yes; TOLERANCE: 1%; Tolerance (%): ± 1%
ST1 ST2 = SHORT
TP8 TP9 TP966-TP970 TP1004 = TP,_0.016_,_Thru_Hole
U122 = LTC4625EY: 20VIN, 5A Step-Down DC/DC µModule Regulator; Item Num: K21464-001; Manufacturer: Linear; Manufacturer Part Num: LTM4625EY#PBF
U123 U124 = LTM4623EY#PBF: Item Num: K15502-001
C1533 = Cap,_NP,_0402: CAP,2.2UF,0402,X6S,25V,+/-20%; Agile Part Number: P03-17965R; CAPACITANCE: 0.1uF; IPN: M13510-001; Item Num: M13510-001; LIFECYCLE_PHASE: Active; Lead Free Status: Lead Free; MFR_LIFECYCLE: Active; Manufacturer: Murata; Manufacturer Part Num: GRM155C81E225ME11D; Num Pins: 2; PART_SUBCLASS: CAPACITORS; PSpiceTemplate: C^@REFDES %1 %2 ?TOLERANCE|C^@REFDES| @VALUE ?IC/IC=@IC/ ?TOLERANCE|\n.model C^@REFDES CAP C=1 DEV=@TOLERANCE%|; Part Class: CAPACITORS; Part Number: GRM155C81E225ME11D; RATED_VOLTAGE: 25V; TOLERANCE: +/-20%; Voltage: 25V
C1625 C1626 C1629 = CAPPOL: CAP, TANT, 330 uF, 10%, 16V, 7343-43, SMD-2P; Item Num: M78371-001; Manufacturer: Kemet; Manufacturer Part Num: T545X337K016ATE025; PACK_TYPE: 7343-43; PART_NUMBER: T545X337K016ATE025; PIN_POLARITY: 1; Package: 2917; Package Size: 2917 (D3L); Part Number: T491X157K020AT; Tolerance: 10%; Voltage: 16V
C1627 = CAPPOL: CAP, TANT, 330 uF, 10%, 16V, 7343-43, SMD-2P; Item Num: M78371-001; Manufacturer: Kemet; Manufacturer Part Num: T545X337K016ATE025; PACK_TYPE: 7343-43; PART_NUMBER: T545X337K016ATE025; PIN_POLARITY: 1; Package: 2917; Package Size: 2917; Part Number: T491X157K020AT; Tolerance: 10%; Voltage: 16V
C1628 = CAPPOL: CAP TANT POLY 330UF 16V 2924; Item Num: M71941-001; Manufacturer: Vishay Polytech; Manufacturer Part Num: T52M1337M016C0040; PACK_TYPE: 7361; PART_NUMBER: T52M1337M016C0040; PIN_POLARITY: 1; Package: 2917; Package Size: 2924; Part Number: T52M1337M016C0040; Tolerance: 10%; Voltage: 16V
C1630-C1633 = Cap,_NP,_1206: CAPC,X6S,1206,22UF,25V,+/- 10%; Agile Part Number: 06593; Dielectric: X5R/X6S; Item Num: H65936-001; Manufacturer: Murata; Manufacturer Part Num: GRM31CC81E226K; Package: 1206; Part Number: GRM31CC81E226K; Structure: MLCC; Voltage: 25V
C1714 = CAP: CAP CER 4.7UF 10V X5R 0402; Item Num: J89506-001; Manufacturer: MURATA; Manufacturer Part Num: ZRB15XR61A475KE01D; Part Number: C1005X5R1A475K050BE; RATED_VOLTAGE: 10V; RoHS Compliant: RoHS Compliant
C1715 C1716 = CAP: CAP, CERAMIC, 2.2UF, 10%, 10VDC, X5R, 0603; Item Num: K13568-001; Manufacturer: Murata; Manufacturer Part Num: GRM188R61A225KE34x; RATED_VOLTAGE: 10V; RoHS Compliant: RoHS Compliant
C1718 = Cap,_NP,_0402: CAP - CER, 1UF, 25V, 10%, X5R, 0402; Agile Part Number: P03-17965R; Item Num: H29050-001; Manufacturer: TDK Electronics; Manufacturer Part Num: CGB2A1X5R1E105K033BC; Part Class: CAPACITORS; Part Number: CGB2A1X5R1E105K033BC; RATED_VOLTAGE: 25V
C1719 = CAP: CAP C,0603,330PF,50VDC,+/-5%; Item Num: K13562-001; Manufacturer: Samsung Electro-Mechanics; Manufacturer Part Num: GRM1885C1H331JA01D; Part Number: GRM1885C1H331JA01D; RATED_VOLATGE: 50V; RoHS Compliant: RoHS Compliant
C1720 = CAP: CAP, CERAMIC, 100pF, 0402, 5%, 50VDC, NPO; Item Num: A36095-026; Manufacturer: Murata; Manufacturer Part Num: 04025C101KAT2A; Part Class: CAPACITORS; RATED_VOLATGE: 50V; RoHS Compliant: RoHS Compliant; Tolerance: 10%
C1721 = CAP: CAP CER2200PF 25V, 0402  10%; Item Num: E24654-001; Manufacturer: TDK Corporation; Manufacturer Part Num: C0402C222K3RAC; Part Number: C0402C222K3RAC; RATED_VOLATGE: 25V; RoHS Compliant: RoHS Compliant
C7664 = Cap,_NP,_0402: CAPC,  X7R, 0402, 0.1uF, 25V, ±20%; Agile Part Number: P03-17965R; Item Num: K13660-001; Manufacturer: Murata; Manufacturer Part Num: GRM155R71E104KE14D; Package: 0402; Part Number: GRM155R71E104KE14D; RATED_VOLTAGE: 25V; Rated Voltage: 25V
C7669-C7672 = CAP: CAP CER 0.47UF 6.3V X6S 0402; AGILE_LINK: http://sj-agile9app/Agile/PLMServlet?action=OpenEmailObject&classid=10000&objid=257560276; Item Num: D97712-012; LIFECYCLE_PHASE: Active; Lead Free Status: Not Lead Free; MFR_LIFECYCLE: Active; Manufacturer: TDK; Manufacturer Part Num: CGB2A3X6S0J474M033BB; Num Pins: 2; PART_SUBCLASS: CAPACITORS; RATED_VOLTAGE: 6.3V; RoHS Compliant: RoHS Compliant; TOLERANCE: 20%; Temperature Coefficient: X6S
C7678 = Cap,_NP,_0402: CAPC,  X7R, 0402, 0.1uF, 25V, ±20%; Agile Part Number: P03-17965R; Item Num: K13660-001; Manufacturer: Murata; Manufacturer Part Num: GRM155R71E104KE14D; Package: 0402; Part Number: GRM155R71E104KE14D; RATED_VOLTAGE: 25V
J12 = 1x3_HDR_TH: 1X3 .100"CENTER HEADER, .145" MIN SOLDER TAIL; Item Num: K12462-001; Manufacturer: Samtec
R546 R547 R926 R6065 R6194 = RES_0_OHM_5%_1_16W_0402_SMD: Item Num: H30887-001; Tolerance: Jumper
R853 = Resistor,_0402_0: RES SMD 0 OHM JUMPER 1/10W 0402; Agile Part Number: 02495; Item Num: K29085-001; Manufacturer: Vishay; Manufacturer Part Num: ERJ-2GE0R00X; Package: 0402; Part Number: ERJ-2GE0R00X; TOLERANCE: ±5%
R5870 = RESISTOR: RES SMD 5.11K OHM 1% 1/16W 0402; Item Num: G64084-187; Lead Free Status: No; Manufacturer: YAGEO; Manufacturer Part Num: AC0402FR-075K11L; Num Pins: 2; Part Class: RESISTORS; Price: 0; RoHS Compliant: Yes; Tolerance: ± 1%
R5871 = RESISTOR: RES SMD 3.09K OHM 1% 1/10W 0402; Item Num: K15767-001; Lead Free Status: No; Manufacturer: Panasonic Electronic; Manufacturer Part Num: ERJ-2RKF3091X; Num Pins: 2; Part Class: RESISTORS; Price: 0; RoHS Compliant: Yes; Tolerance: ± 1%
R5873 = RESISTOR: RES_D,0402,6.49kOHM,1/20W; Item Num: K95130-001; Lead Free Status: No; Manufacturer: YAGEO CORP.; Manufacturer Part Num: RT0402BRD076K49L; Num Pins: 2; Part Class: RESISTORS; Price: 0; RoHS Compliant: Yes; Tolerance: ± 1%
R5875-R5878 R6024 R6025 R6037 R6069 = Resistor,_0402: RES 10K OHM 1/16W 5% 0402 SMD; Agile Part Number: P02-17688R; Item Num: A93549-023; Manufacturer: Yageo; Manufacturer Part Num: RC0402JR-0710KL; Part Number: ERJ-2RKF1002X; Power: 1/16W; TOLERANCE: ± 1%
R5881-R5883 R6035 = RESISTOR: RES,499 OHMS,1.0%,1/16W,0402; Item Num: A93548-094; Lead Free Status: No; Manufacturer: YAGEO; Manufacturer Part Num: RT0402BRE07499RL; Num Pins: 2; Part Class: RESISTORS; Part Number: RT0402BRE07499RL; Price: 0; RoHS Compliant: Yes; Tolerance: 1%
R6026 = RESISTOR: RES_D,0402,18.7kOHM,1.0%,1/16W; Item Num: K67064-001; Lead Free Status: No; Manufacturer: YAGEO CORP.; Manufacturer Part Num: RC0402FR-0718K7L; Num Pins: 2; Part Class: RESISTORS; Price: 0; RoHS Compliant: Yes; Tolerance: ± 1%
R6036 R6273-R6276 = Resistor,_0402: RES 10K OHM 1/16W 5% 0402 SMD; Agile Part Number: P02-17688R; Item Num: A93549-023; Manufacturer: Yageo; Manufacturer Part Num: RC0402JR-0710KL; Part Number: ERJ-2RKF1002X; Power: 1/16W; TOLERANCE: ± 5%
R6195 = RESISTOR: RES_D,0402,6.49kOHM,1.00%,1/16W; Item Num: G21796-165; Lead Free Status: No; Manufacturer: YAGEO CORP; Manufacturer Part Num: RC0402FR-076K49P; Num Pins: 2; Part Class: RESISTORS; Price: 0; RoHS Compliant: Yes; Tolerance: 1%
R6196 = RES_0_OHM_5%_1_16W_0402_SMD: Item Num: H30887-001; Tolerance: ±5%
R6277-R6279 R6291 R6292 = Resistor,_0402_0: RES D,0402,0.00 OHM,5.00%,1/16W; Agile Part Number: 02495; Item Num: A93549-001; Manufacturer: YAGEO CORP.; Manufacturer Part Num: ERJ-2GE0R00X; Package: 0402; Part Number: ERJ-2GE0R00X; Tolerance: ± 5%
U119 = LTC3888IUHG-1#PBF: Buck Regulator Positive Output Step-Down I²C, PMBus DC-DC Controller IC 52-QFN (5x8); Item Num: M76261-001
C1557 C1575 C1622-C1624 C1738 C1749 C7557 = CAPPOL: CAPS,AL-P,V,470.00uF,2.5V,+/- 20%,V,; Item Num: K22160-001; Manufacturer: Panasonic; Manufacturer Part Num: EEFGX0E471R; Package: 2917; Package Size: 2917 (D3L); Part Number: EEFGX0E471R; RATED_VOLTAGE: 2.5V
C1558 C1559 C1576 C1577 C1739 C1750 C1751 C7679 C7680 C7687 C7688 C7693-C7696 = Cap,_NP,_0805: CAPC,X6S,0805,100.00UF,4.00V,+/-20%; Agile Part Number: DNI; Dielectric: X6S; Item Num: H94455-002; Manufacturer: Murata; Manufacturer Part Num: GRM21BC80G107ME15L; Package: 0805; Part Number: GRM21BC80G107ME15L; WVDC: 4V
C1560-C1563 C1578 C1580 C1581 C1732-C1735 C1743-C1746 = Cap,_NP,_1206: CAPC,X6S,1206,22UF,25V,+/- 10%; Agile Part Number: 06593; Dielectric: X5R/X6S; Item Num: H65936-001; Manufacturer: Murata; Manufacturer Part Num: GRM31CC81E226K; Package: 0805; Part Number: GRM31CC81E226K; Structure: MLCC; Voltage: 25V
C1564 C1565 C1582 C7556 = Cap,_NP,_0402: CAPC,X6S,0402,1.00UF,25.00V,+/- 10%; Agile Part Number: 11606; Dielectric: X5R/X6S; Item Num: H81594-001; Manufacturer: Murata; Manufacturer Part Num: GRM155C81E105KE11D; Package: 0402; Part Number: GRM155C81E105KE11D; Structure: MLCC; Voltage: 25V
C1579 = Cap,_NP,_1206: CAPC,X6S,1206,22UF,25V,+/- 10%; Agile Part Number: 06593; Dielectric: X5R/X6S; Item Num: H65936-001; Manufacturer: Murata; Manufacturer Part Num: GRM31CC81E226K; Package: 0805; Part Number: GRM31CC81E226K; RATED_VOLTAGE: 25V; Structure: MLCC; Voltage: 25V
C1728 = Cap,_NP,_0402: CAP CER 10UF 10V X5R 0402; Agile Part Number: P03-17662R; Dielectric: X5R; Item Num: J40971-001; Manufacturer: Samsung Electro-Mechanics; Manufacturer Part Num: CL05A106MP8NUB8; Part Number: CL05A106MP8NUB8; RATED_VOLTAGE: 10V; TOLERANCE: ±10%
C1729 C7580 = Cap,_NP,_0402: CAP - CER, 1uF, 10V, +/-10%, X5R, 0402; Agile Part Number: P03-17662R; Dielectric: X5R; Item Num: G61001-001; Manufacturer: Murata; Manufacturer Part Num: GRM155R61A105KE15D; Part Number: C1005X5R1A475K050BE; RATED_VOLTAGE: 10V; TOLERANCE: ±10%; Voltage: 10V
C7578 C7582 = Cap,_NP,_0402: CAP - CER, 1uF, 10V, +/-10%, X5R, 0402; Agile Part Number: P03-17662R; Dielectric: X5R; Item Num: G61001-001; Manufacturer: Murata; Manufacturer Part Num: GRM155R61A105KE15D; Part Number: C1005X5R1A475K050BE; TOLERANCE: ±10%; Voltage: 10V
C7579 C7581 = Cap,_NP,_0402: CAP CER 10UF 10V X5R 0402; Agile Part Number: P03-17662R; Dielectric: X5R; Item Num: J40971-001; Manufacturer: Samsung Electro-Mechanics; Manufacturer Part Num: CL05A106MP8NUB8; Part Number: C1005X5R1A475K050BE; RATED_VOLTAGE: 10V; TOLERANCE: ±10%; Voltage: 10V
C2028 C7681 C7682 C7686 C7689-C7692 = CAP: CAP CER 47PF 50V C0G/NP0 0402; AGILE_LINK: http://sj-agile9app/Agile/PLMServlet?action=OpenEmailObject&classid=10000&objid=257560276; Item Num: K19455-001; LIFECYCLE_PHASE: Active; Lead Free Status: Not Lead Free; MFR_LIFECYCLE: Active; Manufacturer: Murata; Manufacturer Part Num: GRM1555C1H470FA01D; Num Pins: 2; PART_SUBCLASS: CAPACITORS; RATED_VOLTAGE: 50V; RoHS Compliant: RoHS Compliant; TOLERANCE: 1%; Temperature Coefficient: C0G/NPO
L23 L27-L29 = FP0805R1-R07-R: Item Num: M24459-001
R5884 R6066-R6068 = Resistor,_0402_0: RES D,0402,1 OHM,0.125W,1%,SMD; Agile Part Number: 02495; Item Num: G64013-001; Manufacturer: VISHAY; Manufacturer Part Num: CRCW04021R00FKEDHP; Package: 0402; Part Number: ERJ-2GE0R00X; TOLERANCE: ± 5%
R5885 R5886 R6256 = Resistor,_0402_0: RES D,0402,0.00 OHM,5.00%,1/16W; Agile Part Number: 02495; Item Num: A93549-001; Manufacturer: YAGEO CORP.; Manufacturer Part Num: ERJ-2GE0R00X; Package: 0402; Part Number: ERJ-2GE0R00X; TOLERANCE: ± 5%
R5887 R5888 = Resistor,_0402_0: RES 100 OHM 1/16W .1% 0402,; Agile Part Number: 02495; Item Num: G61554-001; Manufacturer: PANASONIC INDUSTRIAL; Manufacturer Part Num: ERA-2AEB101X; Package: 0402; Part Number: ERA-2AEB101X; TOLERANCE: 0.1%
R6039 R6040 R6255 = Resistor,_0402_0: RES D,0402,0.00 OHM,5.00%,1/16W; Agile Part Number: 02495; Item Num: A93549-001; Manufacturer: YAGEO CORP.; Manufacturer Part Num: RC0402JR-070RL; Package: 0402; Part Number: RC0402JR-070RL; TOLERANCE: ± 5%
R6041 = Resistor,_0603_0: RES D,0603,100.00 OHM,1.00%,1/10W; Agile Part Number: NEW; Item Num: A93550-026; Manufacturer: Yageo; Manufacturer Part Num: RC0603FR-07100RL; Package: 0603; Part Number: RC0603FR-07100RL
U120 U121 U125 U126 = LTC7051AV#PBF: Item Num: M59804-001
C1730 C1731 C1741 C1742 = Cap,_NP,_0402: CAPC,X6S,0402,1.00UF,25.00V,+/- 10%; Agile Part Number: 11606; Dielectric: X5R/X6S; Item Num: H81594-001; Manufacturer: Murata; Manufacturer Part Num: GRM155C81E105KE11D; Part Number: GRM155C81E105KE11D; RATED_VOLTAGE: 25V; Structure: MLCC; Voltage: 25V
C1740 = Cap,_NP,_0805: CAPC,X6S,0805,100.00UF,4.00V,+/-20%; Agile Part Number: DNI; Dielectric: X6S; Item Num: H94455-002; Manufacturer: Murata; Manufacturer Part Num: GRM21BC80G107ME15L; Package: 0805; Part Number: GRM21BC80G107ME15L; RATED_VOLTAGE: 4V; WVDC: 4V
C7572 C7603 C7684 C7685 = Cap,_NP,_1206: CAPC,X6S,1206,22UF,25V,+/- 10%; Agile Part Number: 06593; Dielectric: X5R/X6S; Item Num: H65936-001; Manufacturer: Murata; Manufacturer Part Num: GRM31CC81E226K; Package: 0805; Part Number: GRM31CC81E226K; RATED_VOLTAGE: 25V; Structure: MLCC
C7583 = Cap,_NP,_0402: CAP CER 10UF 10V X5R 0402; Agile Part Number: P03-17662R; Dielectric: X5R; Item Num: J40971-001; Manufacturer: Samsung Electro-Mechanics; Manufacturer Part Num: CL05A106MP8NUB8; Part Number: C1005X5R1A475K050BE; TOLERANCE: ±10%; Voltage: 10V
C7602 = CAP: CAPC,X6S,0402,1.00UF,25.00V,+/- 10%; Item Num: H81594-001; Lead Free Status: Yes; Manufacturer: Murata; Manufacturer Part Num: GRM155C81E105KE11D; Num Pins: 2; Part Class: CAPACITORS; RATED_VOLTAGE: 25V; RoHS Compliant: Yes; Temperature Coefficient: X6S; Voltage: 25V
C7654 = CAP: CAPC,  X7R, 0402, 0.1uF, 25V, ±20%; Dielectric: X6S; Item Num: K13660-001; LIFECYCLE_PHASE: Active; Lead Free Status: Lead Free; Manufacturer: Murata; Manufacturer Part Num: GRM155C81E104KA12D; Num Pins: 2; Part Class: CAPACITORS; Part Number: GRM155C81E104KA12D; RATED_VOLTAGE: 25V; RoHS Compliant: RoHS Compliant; Tolerance: 10%
C7665 = CAP: CAP - CER, 10NF, 50V, +/-10%, X7R, 0402 SMD; AGILE_LINK: http://sj-agile9app/Agile/PLMServlet?action=OpenEmailObject&classid=10000&objid=213459527; CAPACITANCE: 0.1uF; Item Num: A36096-100; LIFECYCLE_PHASE: Active; Lead Free Status: Lead Free; MFR_LIFECYCLE: Active; Manufacturer: Murata; Manufacturer Part Num: GRM155R71H103KA88D; Num Pins: 2; PART_SUBCLASS: CAPACITORS; Part Class: CAPACITORS; RATED_VOLTAGE: 50V; RoHS Compliant: RoHS Compliant; TOLERANCE: +/-10%
C7683 = CAP: CAP, CERAMIC, 100pF, 0402, 5%, 50VDC, NPO; CAPACITANCE: 1000pF; Dielectric: X7R; IPN No: A36095-026; Item Num: A36095-026; LIFECYCLE_PHASE: Active; Lead Free Status: Lead Free; Manufacturer: Murata; Manufacturer Part Num: 04025C101KAT2A; Num Pins: 2; Part Class: CAPACITORS; Part Number: 04025C101KAT2A; RATED_VOLTAGE: 50V; RoHS Compliant: RoHS Compliant; Tolerance: 10%
R5890 R5891 R5893 R5894 R6257 R6258 = Resistor,_0402_0: RES D,0402,0.00 OHM,5.00%,1/16W; Agile Part Number: 02495; Item Num: A93549-001; Manufacturer: YAGEO CORP.; Manufacturer Part Num: RC0402JR-070RL; Package: 0402; Part Number: ERJ-2GE0R00X; TOLERANCE: ± 5%
R6053 = Resistor,_0402: RES,4.12KOHM,1/16W,1%,0402,SMD; Agile Part Number: P02-17129R; Item Num: D83700-001; Manufacturer: ROHM CO., LTD.; Manufacturer Part Num: MCR01MZPF4121; Part Number: ERJ-2RKF1003X; Power: 1/16W; TOLERANCE: ±1.0%
R6074 = Resistor,_0402: RES_D,0402,215kOHM,0.01%,1/10W; Agile Part Number: P02-17688R; Item Num: K21634-001; Manufacturer: PANASONIC ELECTRONIC DEVICES CO. LTD.; Manufacturer Part Num: ERJ-S02F2153X; Part Number: ERJ-2RKF1002X; Power: 1/16W; TOLERANCE: ± 0.01%
R6075 = Resistor,_0402_0: RES D,0402,0.00 OHM,5.00%,1/16W; Agile Part Number: 02495; Item Num: A93549-001; Manufacturer: YAGEO CORP.; Manufacturer Part Num: RC0402JR-070RL; Package: 0402; Part Number: ERJ-2GE0R00X; TOLERANCE: ±5%
R6076 = RESISTOR: RES,100K OHMS,1.0%,1/16W,0402; Item Num: A78422-001; Lead Free Status: No; Manufacturer: Panasonic; Manufacturer Part Num: ERJ-2RKF1003X; Num Pins: 2; Part Class: Resistors; Price: 0; RoHS Compliant: Yes; TOLERANCE: ± 1%
U116 = LTM4622EV#PBF: Item Num: J24671-001; Part Number: LINEAR TECH. LTM4622EV#PBF

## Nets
5V: C721.1 C722.1 C723.1 C724.1 C725.2 C7626.2 C7630.2 C7640.2 C7646.2 R586.1 R6102.2 R6108.1 R6119.1 R6132.2 U122.C1(VOUT1) U122.D1(VOUT2) U122.D2(VOUT3) U122.E1(VOUT4) U122.E2(VOUT5) U123.D5(VIN1) U123.E5(VIN2) U124.D5(VIN1) U124.E5(VIN2) ; also on sheet 48 59 65 68 73
5V_AGND: C720.1 C726.1 C727.1 R584.2 R588.2 R590.1 U122.B4(SGND)
5V_PG: R578.1 R579.1 U122.C2(PGOOD) ; also on sheet 50
12V_G1: C1533.2 C1560.2 C1561.2 C1562.2 C1563.2 C1564.1 C1565.1 C1578.2 C1579.2 C1580.2 C1581.2 C1582.1 C1625.1(p) C1626.1(p) C1627.1(p) C1628.1(p) C1629.1(p) C1630.2 C1631.2 C1632.2 C1633.2 C1730.1 C1731.1 C1732.2 C1733.2 C1734.2 C1735.2 C1741.1 C1742.1 C1743.2 C1744.2 C1745.2 C1746.2 C7556.1 C7602.2 C7603.2 C7685.2 R6069.2 U116.A2(VIN2_1) U116.B3(VIN2_2) U116.D3(VIN1_1) U116.E2(VIN1_2) U119.32(VIN) U120.20(VIN1) U120.21(VIN2) U120.37(VIN3) U120.38(VIN4) U120.43(VIN5) U121.20(VIN1) U121.21(VIN2) U121.37(VIN3) U121.38(VIN4) U121.43(VIN5) U125.20(VIN1) U125.21(VIN2) U125.37(VIN3) U125.38(VIN4) U125.43(VIN5) U126.20(VIN1) U126.21(VIN2) U126.37(VIN3) U126.38(VIN4) U126.43(VIN5) ; also on sheet 19 20 50 53
12V_G2: C717.2 C718.2 C719.2 R580.1 R587.2 TP968.1 U122.D5(VIN1) U122.E5(VIN2) ; also on sheet 53 58 59 60 61 62 63 64 65 66 67 69 70 71 73
AGND_2p5V_PRE: C7643.2 R6100.1 ST1.1
AGND_3p3V_STBY: C7642.2 R6103.1 ST2.1
GND: C715.1 C716.1 C717.1 C718.1 C719.1 C721.2 C722.2 C723.2 C724.2 C1533.1 C1557.2(n) C1558.1 C1559.1 C1560.1 C1561.1 C1562.1 C1563.1 C1564.2 C1565.2 C1575.2(n) C1576.1 C1577.1 C1578.1 C1579.1 C1580.1 C1581.1 C1582.2 C1622.2(n) C1623.2(n) C1624.2(n) C1625.2(n) C1626.2(n) C1627.2(n) C1628.2(n) C1629.2(n) C1630.1 C1631.1 C1632.1 C1633.1 C1714.2 C1715.2 C1716.2 C1718.1 C1719.2 C1720.2 C1721.2 C1728.1 C1729.1 C1730.2 C1731.2 C1732.1 C1733.1 C1734.1 C1735.1 C1738.2(n) C1739.1 C1740.1 C1741.2 C1742.2 C1743.1 C1744.1 C1745.1 C1746.1 C1749.2(n) C1750.1 C1751.1 C2028.1 C7556.2 C7557.2(n) C7572.1 C7578.1 C7579.1 C7580.1 C7581.1 C7582.1 C7583.1 C7602.1 C7603.1 C7626.1 C7627.1 C7630.1 C7631.1 C7632.1 C7634.1 C7640.1 C7641.1 C7646.1 C7647.1 C7654.1 C7664.1 C7665.2 C7669.1 C7670.1 C7671.1 C7672.1 C7679.1 C7680.1 C7681.2 C7682.2 C7684.1 C7685.1 C7686.1 C7687.1 C7688.1 C7689.1 C7690.1 C7691.2 C7692.2 C7693.1 C7694.1 C7695.1 C7696.1 C7697.1 C7699.1 C7700.1 C7701.1 J12.3 R579.2 R585.2 R588.1 R589.2 R5870.1 R5871.1 R5873.1 R5876.2 R5888.2 R6026.1 R6037.2 R6041.1 R6053.2 R6074.2 R6075.2 R6098.1 R6101.1 R6195.2 R6196.1 ST1.2 ST2.2 U116.B5(GND) U116.C1(GND) U116.C2(GND) U116.D5(GND) U119.40(VSENSE1+) U119.41(VSENSE1-) U119.53(GND) U120.7(PGND) U120.8(PGND) U120.9(PGND) U120.17(PGND) U120.18(PGND) U120.19(PGND) U120.27(PGND) U120.31(SGND) U120.39(PGND) U120.40(PGND) U120.41(PGND) U121.7(PGND) U121.8(PGND) U121.9(PGND) U121.17(PGND) U121.18(PGND) U121.19(PGND) U121.27(PGND) U121.31(SGND) U121.39(PGND) U121.40(PGND) U121.41(PGND) U122.B3(PGND1) U122.C3(PGND2) U122.D3(PGND3) U122.D4(PGND4) U122.E3(PGND6) U123.B3(GND) U123.B4(SGND) U123.C3(GND) U123.D3(GND) U123.D4(GND) U123.E3(GND) U124.B3(GND) U124.B4(SGND) U124.C3(GND) U124.D3(GND) U124.D4(GND) U124.E3(GND) U125.7(PGND) U125.8(PGND) U125.9(PGND) U125.17(PGND) U125.18(PGND) U125.19(PGND) U125.27(PGND) U125.31(SGND) U125.39(PGND) U125.40(PGND) U125.41(PGND) U126.7(PGND) U126.8(PGND) U126.9(PGND) U126.17(PGND) U126.18(PGND) U126.19(PGND) U126.27(PGND) U126.31(SGND) U126.39(PGND) U126.40(PGND) U126.41(PGND) ; also on sheet 9 10 11 13 14 15 16 17 18 19 20 21 22 23 25 26 27 28 29 30 31 32 33 34 35 36 38 39 40 41 42 43 44 45 46 47 48 49 50 51 52 53 58 59 60 61 62 63 64 65 66 67 68 69 70 71 72 73 74 75 76 77
PVCC: C1728.2 C7572.2 C7579.2 C7581.2 C7583.2 C7654.2 C7683.2 C7684.2 R5884.2 R6066.2 R6067.2 R6068.2 U116.A1(VOUT2_1) U116.B1(VOUT2_2) U116.D1(VOUT1_2) U116.E1(VOUT1_1) U120.28(PVCC) U120.29(PVCC) U121.28(PVCC) U121.29(PVCC) U125.28(PVCC) U125.29(PVCC) U126.28(PVCC) U126.29(PVCC)
2p5V_PRE: C7634.2 C7647.2 C7701.2 C7702.2 TP970.1 U124.C1(VOUT1) U124.D1(VOUT2) U124.D2(VOUT3) U124.E1(VOUT4) U124.E2(VOUT5) ; also on sheet 51
3p3V: R853.1 R5877.2 R5878.2 R6024.2 R6025.2 R6036.2 R6292.2 ; also on sheet 58 59 63 65 66 67 69 70 71 72 73 74
3p3V_STBY: C7632.2 C7641.2 C7698.2 C7699.2 TP969.1 U123.C1(VOUT1) U123.D1(VOUT2) U123.D2(VOUT3) U123.E1(VOUT4) U123.E2(VOUT5) ; also on sheet 30 44 48 49 50 51 52 53 77
CORE_PMBUS_SCL: R546.1 ; also on sheet 46
CORE_PMBUS_SDA: R547.1 ; also on sheet 46
DAOUT0: C7678.2 R5875.1 R6291.2 U119.11(DAOUT0)
ED_PMBUS_ALERTn: R926.1 ; also on sheet 48
FAULT: R6024.1 R6025.1 R6065.1 R6255.1 R6256.1 R6257.1 R6258.1 U119.18(~{FAULT0})
FPGA_VCC: C1557.1(p) C1558.2 C1559.2 C1575.1(p) C1576.2 C1577.2 C1622.1(p) C1623.1(p) C1624.1(p) C1738.1(p) C1739.2 C1740.2 C1749.1(p) C1750.2 C1751.2 C7557.1(p) C7679.2 C7680.2 C7687.2 C7688.2 C7693.2 C7694.2 C7695.2 C7696.2 L23.2 L27.2 L28.2 L29.2 R5887.2 R6041.2 TP966.1 TP967.1 ; also on sheet 37 75 77
FPGA_VCC_EN: R853.2 R6037.1 U119.20(RUN0) ; also on sheet 50
FPGA_VCC_PG: C7664.2 R6036.1 R6279.1 R6291.1 ; also on sheet 50
INTVCC_PVCC: R6076.2 U116.C3(INTVCC)
IREF: C1718.2 R6194.2 U119.33(IREF) U119.43(ISENSE1) U119.44(ISENSE7) U119.47(ISENSE6) U119.48(ISENSE5)
ISENSE0: R5883.2 U119.4(ISENSE0) U120.33(ISNS)
ISENSE2: R5881.2 U119.3(ISENSE2) U125.33(ISNS)
ISENSE3: R6035.2 U119.52(ISENSE3) U126.33(ISNS)
ISENSE4: R5882.2 U119.51(ISENSE4) U121.33(ISNS)
ITH0: C1720.1 U119.9(ITH0)
ITHR0: C1721.1 U119.10(ITHR0)
LT4625_INTVCC: C715.2 R578.2 R581.2 R582.2 R583.2 U122.E4(INTVCC)
LTM3888_ALERTn: R926.2 U119.17(~{ALERT})
LTM3888_SCL: J12.1 R546.2 U119.15(SCL)
LTM3888_SDA: J12.2 R547.2 U119.16(SDA)
LTM4623_INTVCC1: C7697.2 R6111.2 R6219.1 U123.E4(INTVCC)
LTM4623_INTVCC2: C7700.2 R6115.2 R6220.1 U124.E4(INTVCC)
PWM0: R6040.1 U119.5(PWM0)
PWM2: R5891.1 U119.2(PWM2)
PWM3: R5894.1 U119.1(PWM3)
PWM4: R5886.1 U119.50(PWM4)
RUN0: C7578.2 R6066.1 R6273.1 U120.30(VCC)
RUN1: C1729.2 R5884.1 R6274.1 U121.30(VCC)
RUN2: C7580.2 R6067.1 R6275.1 U125.30(VCC)
RUN3: C7582.2 R6068.1 R6276.1 U126.30(VCC)
SH_CLK: R5878.1 U119.29(SHARE_CLK)
SW_U120_FPGA_VCC: L27.1 U120.1(SW1) U120.2(SW1) U120.3(SW1) U120.4(SW1) U120.5(SW1) U120.6(SW1) U120.10(SW2_1) U120.11(SW2_2) U120.12(SW2_3) U120.13(SW2_4) U120.14(SW2_5) U120.15(SW2_6) U120.16(SW2_7) U120.42(SW1_7)
SW_U121_FPGA_VCC: L28.1 U121.1(SW1) U121.2(SW1) U121.3(SW1) U121.4(SW1) U121.5(SW1) U121.6(SW1) U121.10(SW2_1) U121.11(SW2_2) U121.12(SW2_3) U121.13(SW2_4) U121.14(SW2_5) U121.15(SW2_6) U121.16(SW2_7) U121.42(SW1_7)
SW_U125_FPGA_VCC: L23.1 U125.1(SW1) U125.2(SW1) U125.3(SW1) U125.4(SW1) U125.5(SW1) U125.6(SW1) U125.10(SW2_1) U125.11(SW2_2) U125.12(SW2_3) U125.13(SW2_4) U125.14(SW2_5) U125.15(SW2_6) U125.16(SW2_7) U125.42(SW1_7)
SW_U126_FPGA_VCC: L29.1 U126.1(SW1) U126.2(SW1) U126.3(SW1) U126.4(SW1) U126.5(SW1) U126.6(SW1) U126.10(SW2_1) U126.11(SW2_2) U126.12(SW2_3) U126.13(SW2_4) U126.14(SW2_5) U126.15(SW2_6) U126.16(SW2_7) U126.42(SW1_7)
SYNC: R5877.1 U119.14(SYNC)
TMON0: C7686.2 R6039.1 U120.22(TMON)
TMON1: C7689.2 R5885.1 U121.22(TMON)
TMON3: C2028.2 R5890.1 U125.22(TMON)
TMON4: C7690.2 R5893.1 U126.22(TMON)
TSNS0: C1719.1 R5885.2 R5890.2 R5893.2 R6039.2 U119.8(TSNS0/VDR_MON)
VFB0: C7678.1 R5875.2 R5876.1 U119.12(VFB0)
VSENSE0+: R5887.1 R6277.1 ; also on sheet 37
VSENSE0+_U119: R6277.2 U119.7(VSENSE0+)
VSENSE0-: R5888.1 R6278.1 ; also on sheet 37
VSENSE0-_U119: R6278.2 U119.6(VSENSE0-)
N31314586: TP8.1 U122.B5(CLKOUT)
N31314601: TP9.1 U122.A5(CLKIN)
N31314621: C716.2 R580.2 U122.C5(SVIN)
N31314744: R582.1 U122.B2(PHMODE)
N31314754: C720.2 R581.1 U122.A1(COMP)
N31314797: R583.1 R585.1 U122.C4(MODE)
N31314853: R584.1 U122.A4(FREQ)
N31314899: C726.2 U122.A2(TRACK/SS)
N31314949: R587.1 R589.1 U122.A3(RUN)
N31314957: C725.1 C727.2 R586.2 R590.2 U122.B1(FB)
N47788591: C1714.1 U119.31(INTVCC)
N47788598: C1716.1 U119.30(VDD33)
N47788631: C1715.1 U119.28(VDD25)
N47788711: R6026.2 U119.22(RSET)
N47788713: R5870.2 U119.23(ASEL0)
N47788715: R5871.2 U119.24(ASEL1)
N47788717: R5873.2 U119.25(ILIM0_CFG)
N47790152: C7669.2 C7670.2 C7671.2 C7672.2 R5881.1 R5882.1 R5883.1 R6035.1 R6194.1
N47791843: R6040.2 U120.35(PWM)
N47793696: R5886.2 U121.35(PWM)
N47795663: R5891.2 U125.35(PWM)
N47798128: R5894.2 U126.35(PWM)
N48280620: R6098.2 U124.A4(FREQ)
N48280647: C7627.2 U124.A2(TRACK/SS)
N48285679: R6108.2 U123.C5(SVIN)
N48285771: R6101.2 U123.A4(FREQ)
N48285810: C7631.2 U123.A2(TRACK/SS)
N48285872: R6102.1 U123.A3(RUN)
N48285918: C7698.1 R6103.2 U123.B1(FB)
N48553342: R6076.1 TP1004.1 U116.B4(PGOOD2) U116.D4(PGOOD1)
N48553533: R6069.1 U116.B2(RUN2) U116.D2(RUN1)
N48553549: U116.A5(COMP2) U116.E5(COMP1)
N48553573: R6075.1 U116.C5(SYNC_MODE)
N48553577: C7665.1 U116.A3(TRACK_SS2) U116.E3(TRACK_SS1)
N48553581: C7683.1 R6053.1 U116.A4(FB2) U116.E4(FB1)
N48553597: R6074.1 U116.C4(FREQ)
N48746840: R6109.2 U123.C4(MODE)
N48746952: R6110.2 U123.B2(PHMODE)
N48746955: R6109.1 R6110.1 R6111.1 R6112.2
N48747048: C7642.1 R6112.1 U123.A1(COMP)
N48779487: C7643.1 R6116.1 U124.A1(COMP)
N48779506: R6115.1 R6116.2 R6117.1 R6118.1
N48779510: R6117.2 U124.B2(PHMODE)
N48779522: R6118.2 U124.C4(MODE)
N48779884: R6119.2 U124.C5(SVIN)
N48792622: R6132.1 U124.A3(RUN)
N48797650: C7702.1 R6100.2 U124.B1(FB)
N49421487: R6196.2 U119.21(RUN1)
N49460376: C7681.1 U121.36(TDIO)
N49467702: C7682.1 U120.36(TDIO)
N49512760: C7691.1 U126.36(TDIO)
N49513184: C7692.1 U125.36(TDIO)
N49665924: R6219.2 U123.C2(PGOOD)
N49666814: R6220.2 U124.C2(PGOOD)
N49934644: R6255.2 U120.34(FLTB)
N49934684: R6256.2 U121.34(FLTB)
N49934953: R6257.2 U125.34(FLTB)
N49934989: R6258.2 U126.34(FLTB)
N50087078: R6273.2 U120.32(RUN)
N50087130: R6274.2 U121.32(RUN)
N50087259: R6275.2 U125.32(RUN)
N50087315: R6276.2 U126.32(RUN)
N51307354: R6195.1 U119.27(PWM_CFG)
N51308385: R6065.2 U119.19(~{FAULT1})
N51791916: R6279.2 U119.13(PGOOD0/CLKOUT)
N51798670: R6292.1 U119.35(VFB1)

Not connected (* = marked no-connect by the designer): U119 26(ILIM1_CFG)* 34(PGOOD1)* 36(DAOUT1)* 37(ITHR1)* 38(ITH1)* 39(TSNS1)* 42(PWM1)* 45(PWM7)* 46(PWM6)* 49(PWM5)*; U120 23(NC4)* 24(NC3)* 25(NC2)* 26(NC1)*; U121 23(NC4)* 24(NC3)* 25(NC2)* 26(NC1)*; U123 A5(CLKIN)* B5(CLKOUT)*; U124 A5(CLKIN)* B5(CLKOUT)*; U125 23(NC4)* 24(NC3)* 25(NC2)* 26(NC1)*; U126 23(NC4)* 24(NC3)* 25(NC2)* 26(NC1)*

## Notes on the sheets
sheet 54
- VCC Core   Controller
- Default Core Voltage = 0.8V
- Note: Place near to IC on PCB
- Note:
- For LTC 3888-1
  Unmount = R6291
  For LTC 3888,
  Unmount = R5875, R5876, R6279
  Mount = R6291
- Note:
  PWM_CFG: 4+1
  0,2,3,4 Channels Used
- PM Bus ADDR = 47h
- IOUT_OC_WARN_LIMIT : 44A
sheet 55
- VCC Core   Phase 1 - 2
- TMON OUTPUT: 8mV/°C
- VCC Core (0.8V)
- PHASE 1
- VCC Core (0.8V)
- PHASE 2
sheet 56
- VCC Core   Phase 3 - 4
- NOTE: Part Attributes of
  components on this page may not
  match up to the component's
  manufacturer's part number!
- TMON OUTPUT: 8mV/°C
- VCC Core (0.8V)
- PHASE 3
- FSW = 2.5MHz
- VCC Core (0.8V)
- PHASE 4
sheet 57
- 12V to 5V, 3p3V STBY, 2p5V_PRE
- 5.0V
- AGND
